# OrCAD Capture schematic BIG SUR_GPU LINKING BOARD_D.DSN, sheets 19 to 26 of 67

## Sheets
19 P19  PLX Switch-2 S4: size Custom
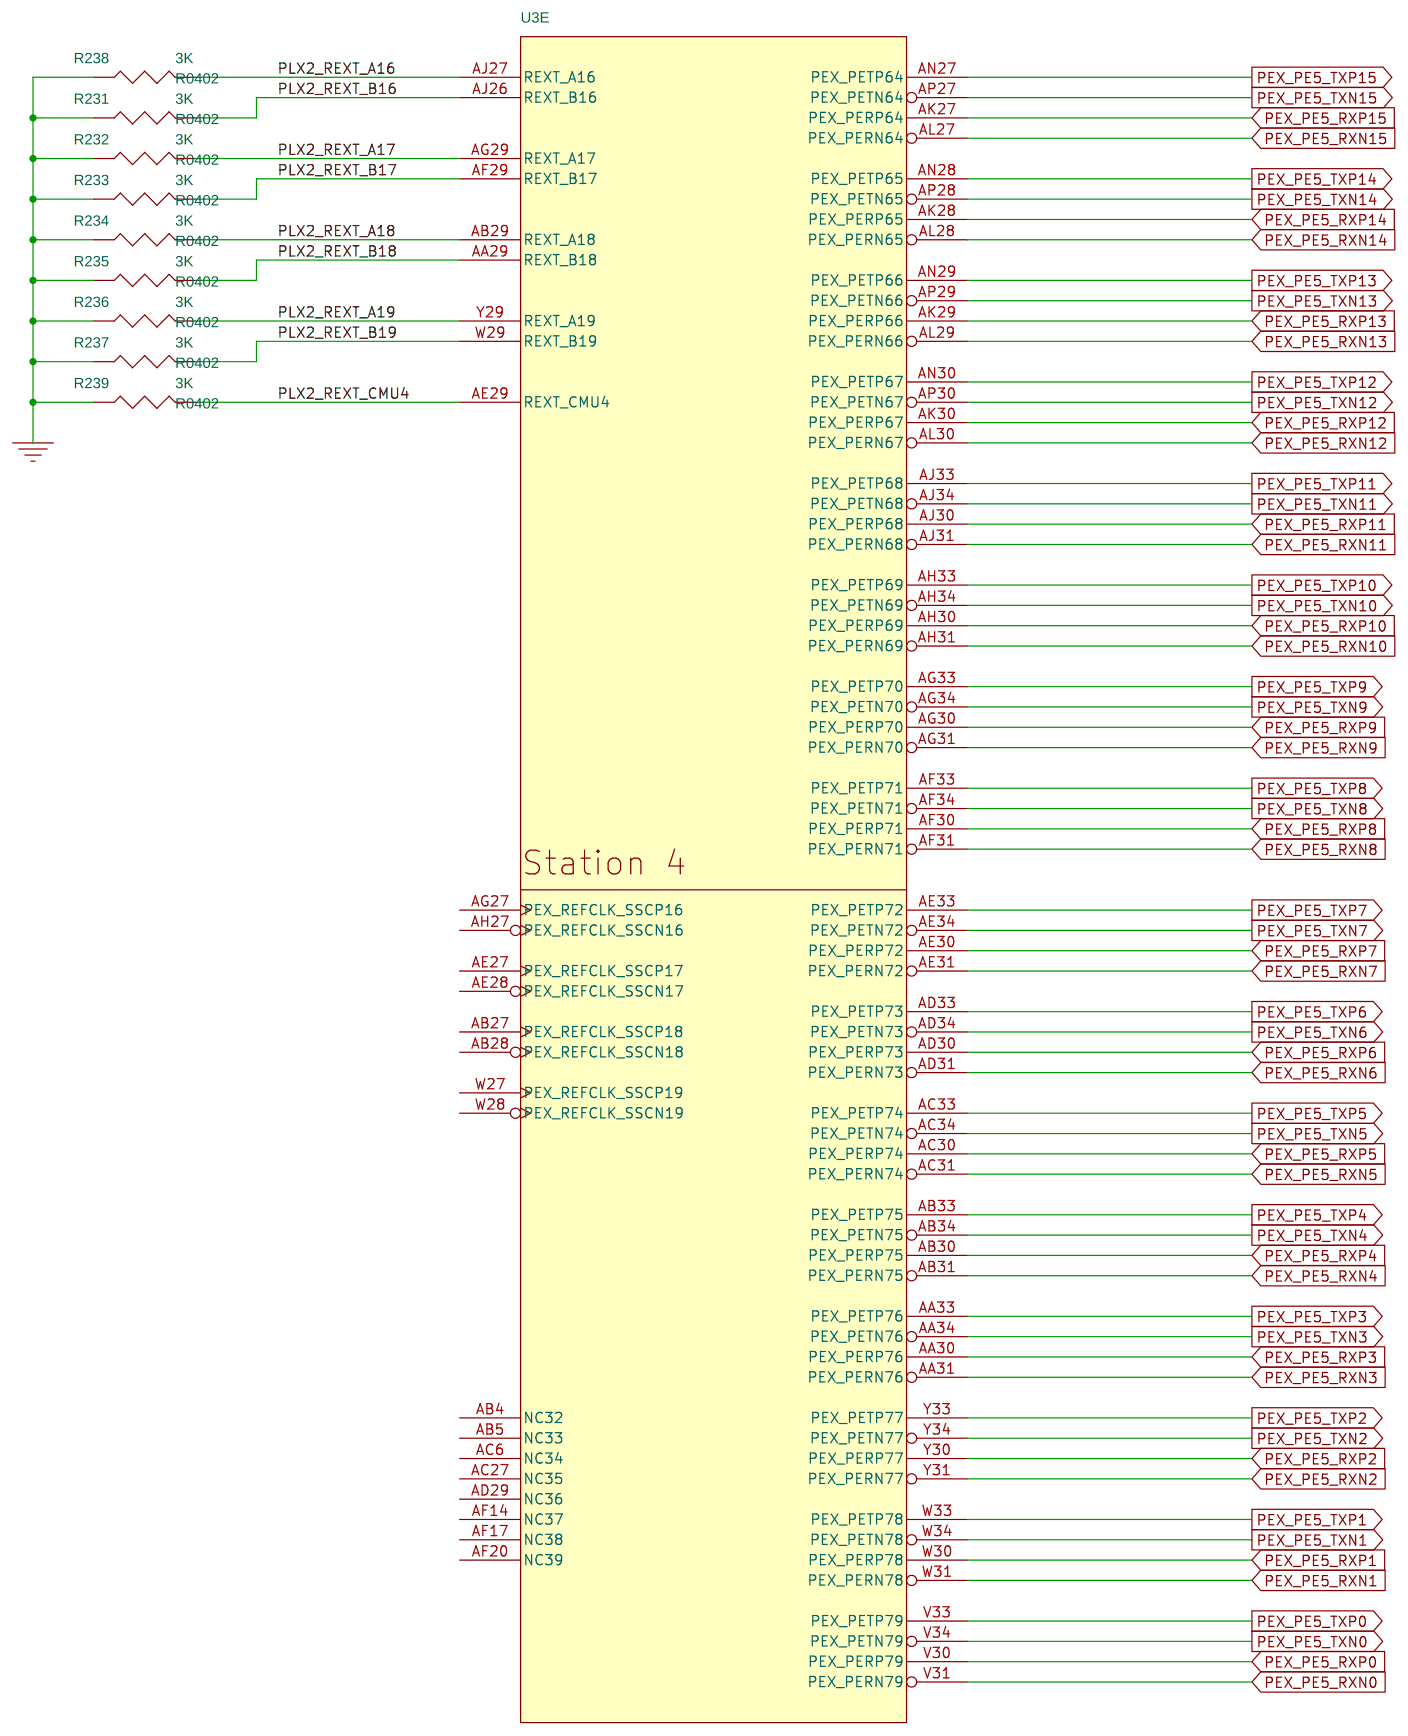
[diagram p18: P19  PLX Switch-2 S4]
20 P20  PLX Switch-2 S5: size Custom
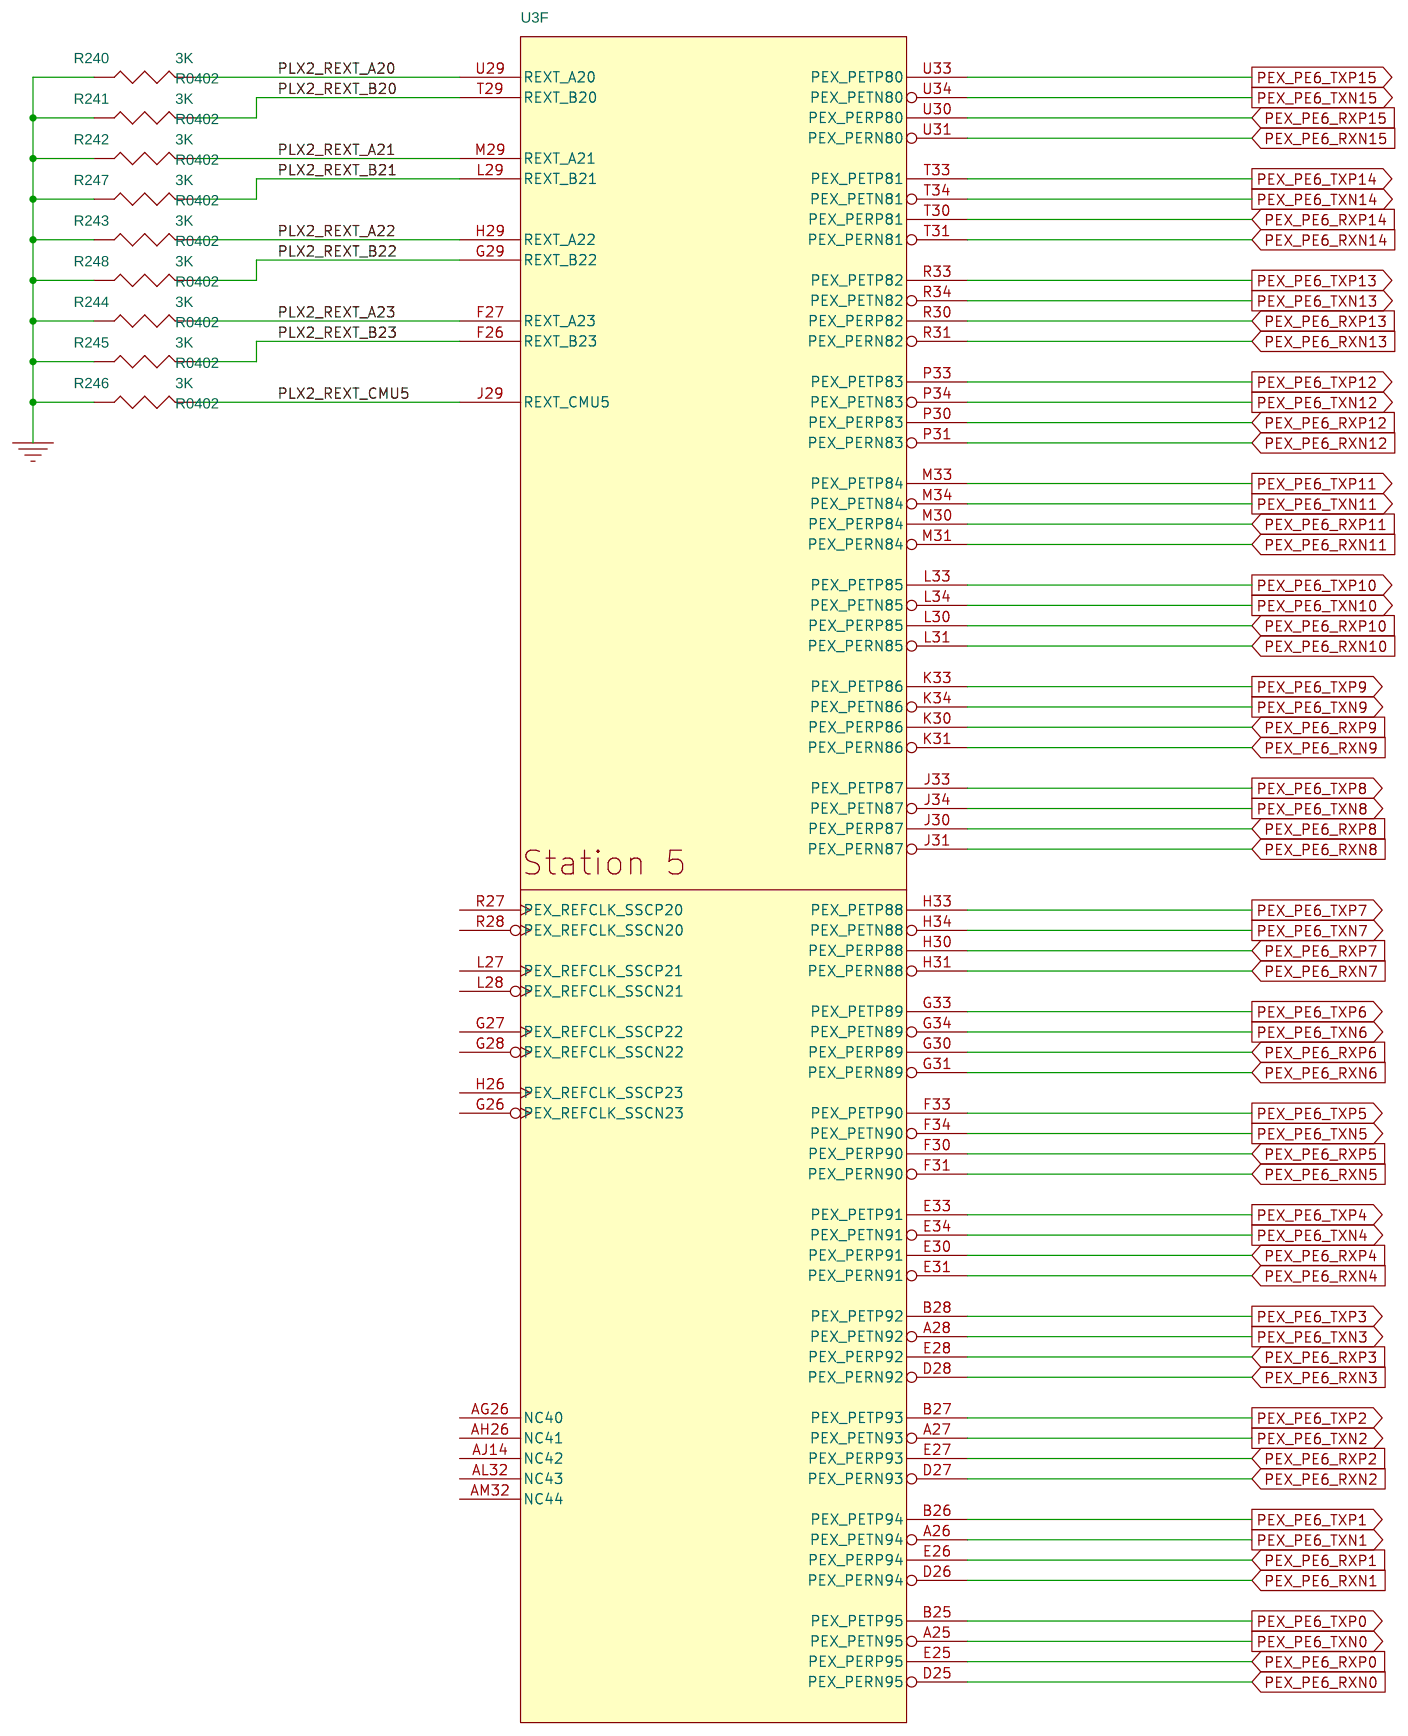
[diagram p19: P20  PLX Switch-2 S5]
21 P21  PLX Switch-2 Mode Select: size C
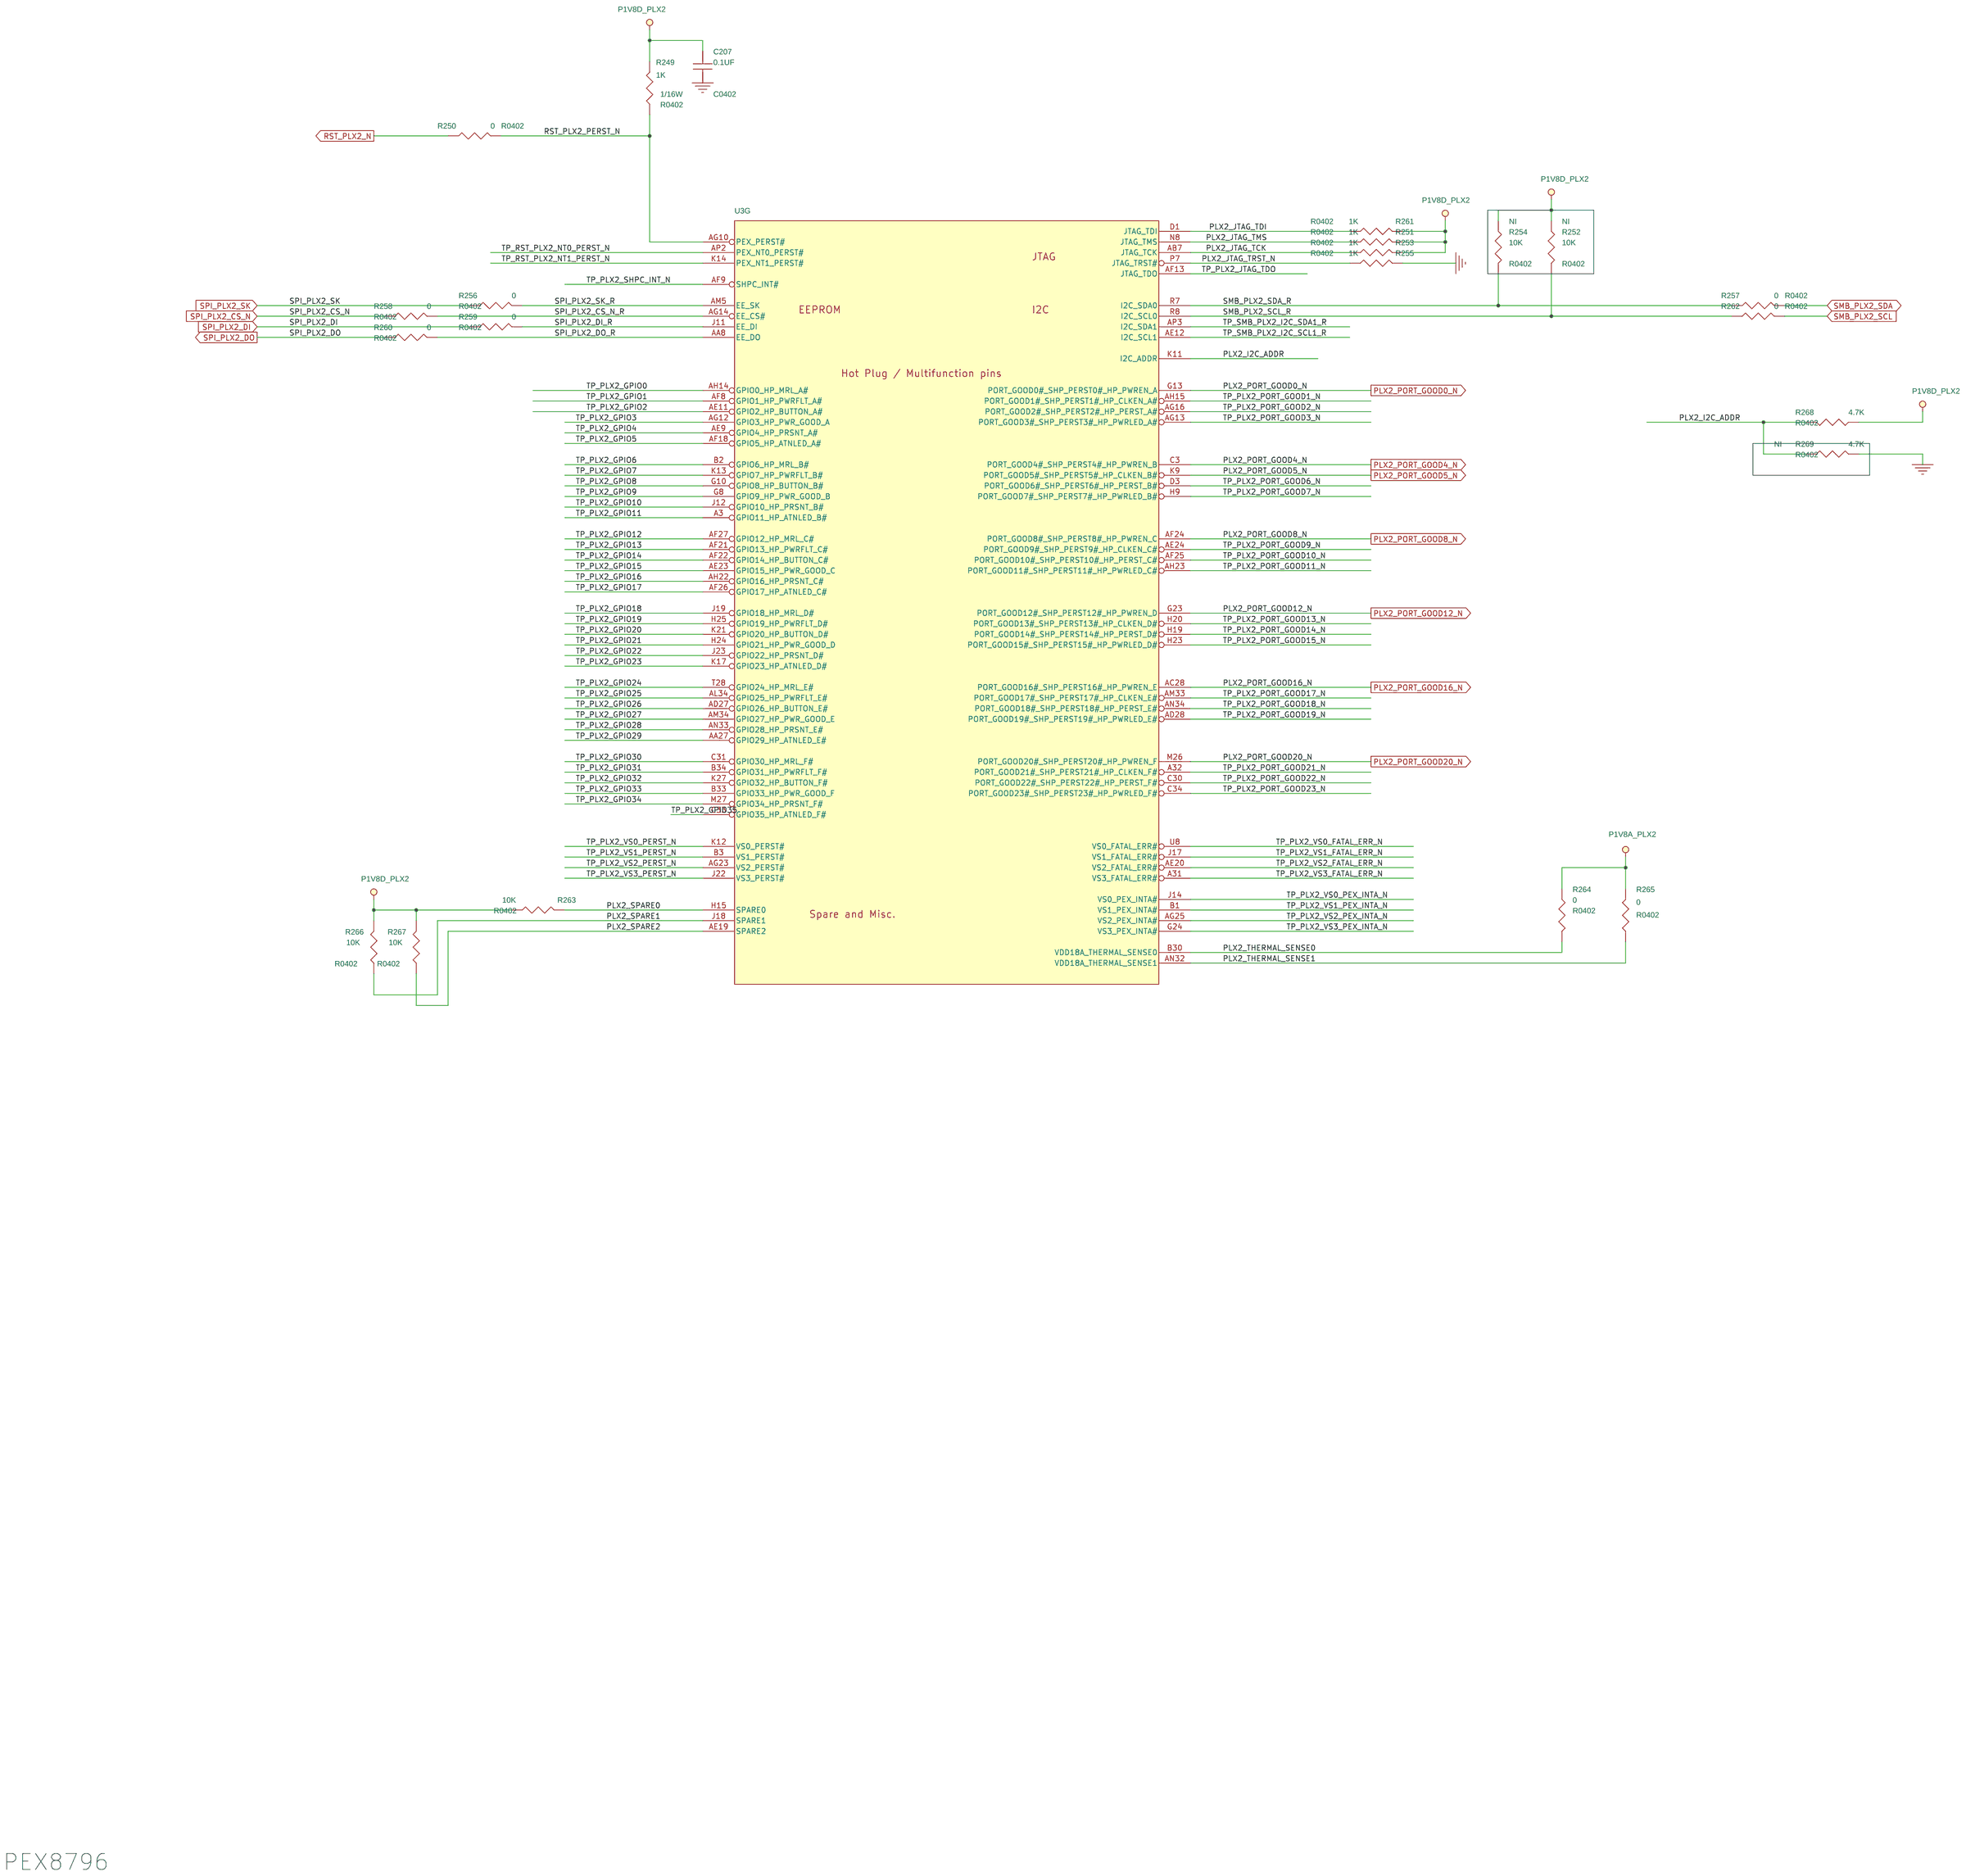
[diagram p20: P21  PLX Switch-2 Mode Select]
22 P22  PLX SW-2 EEPROM & Port LED: size C
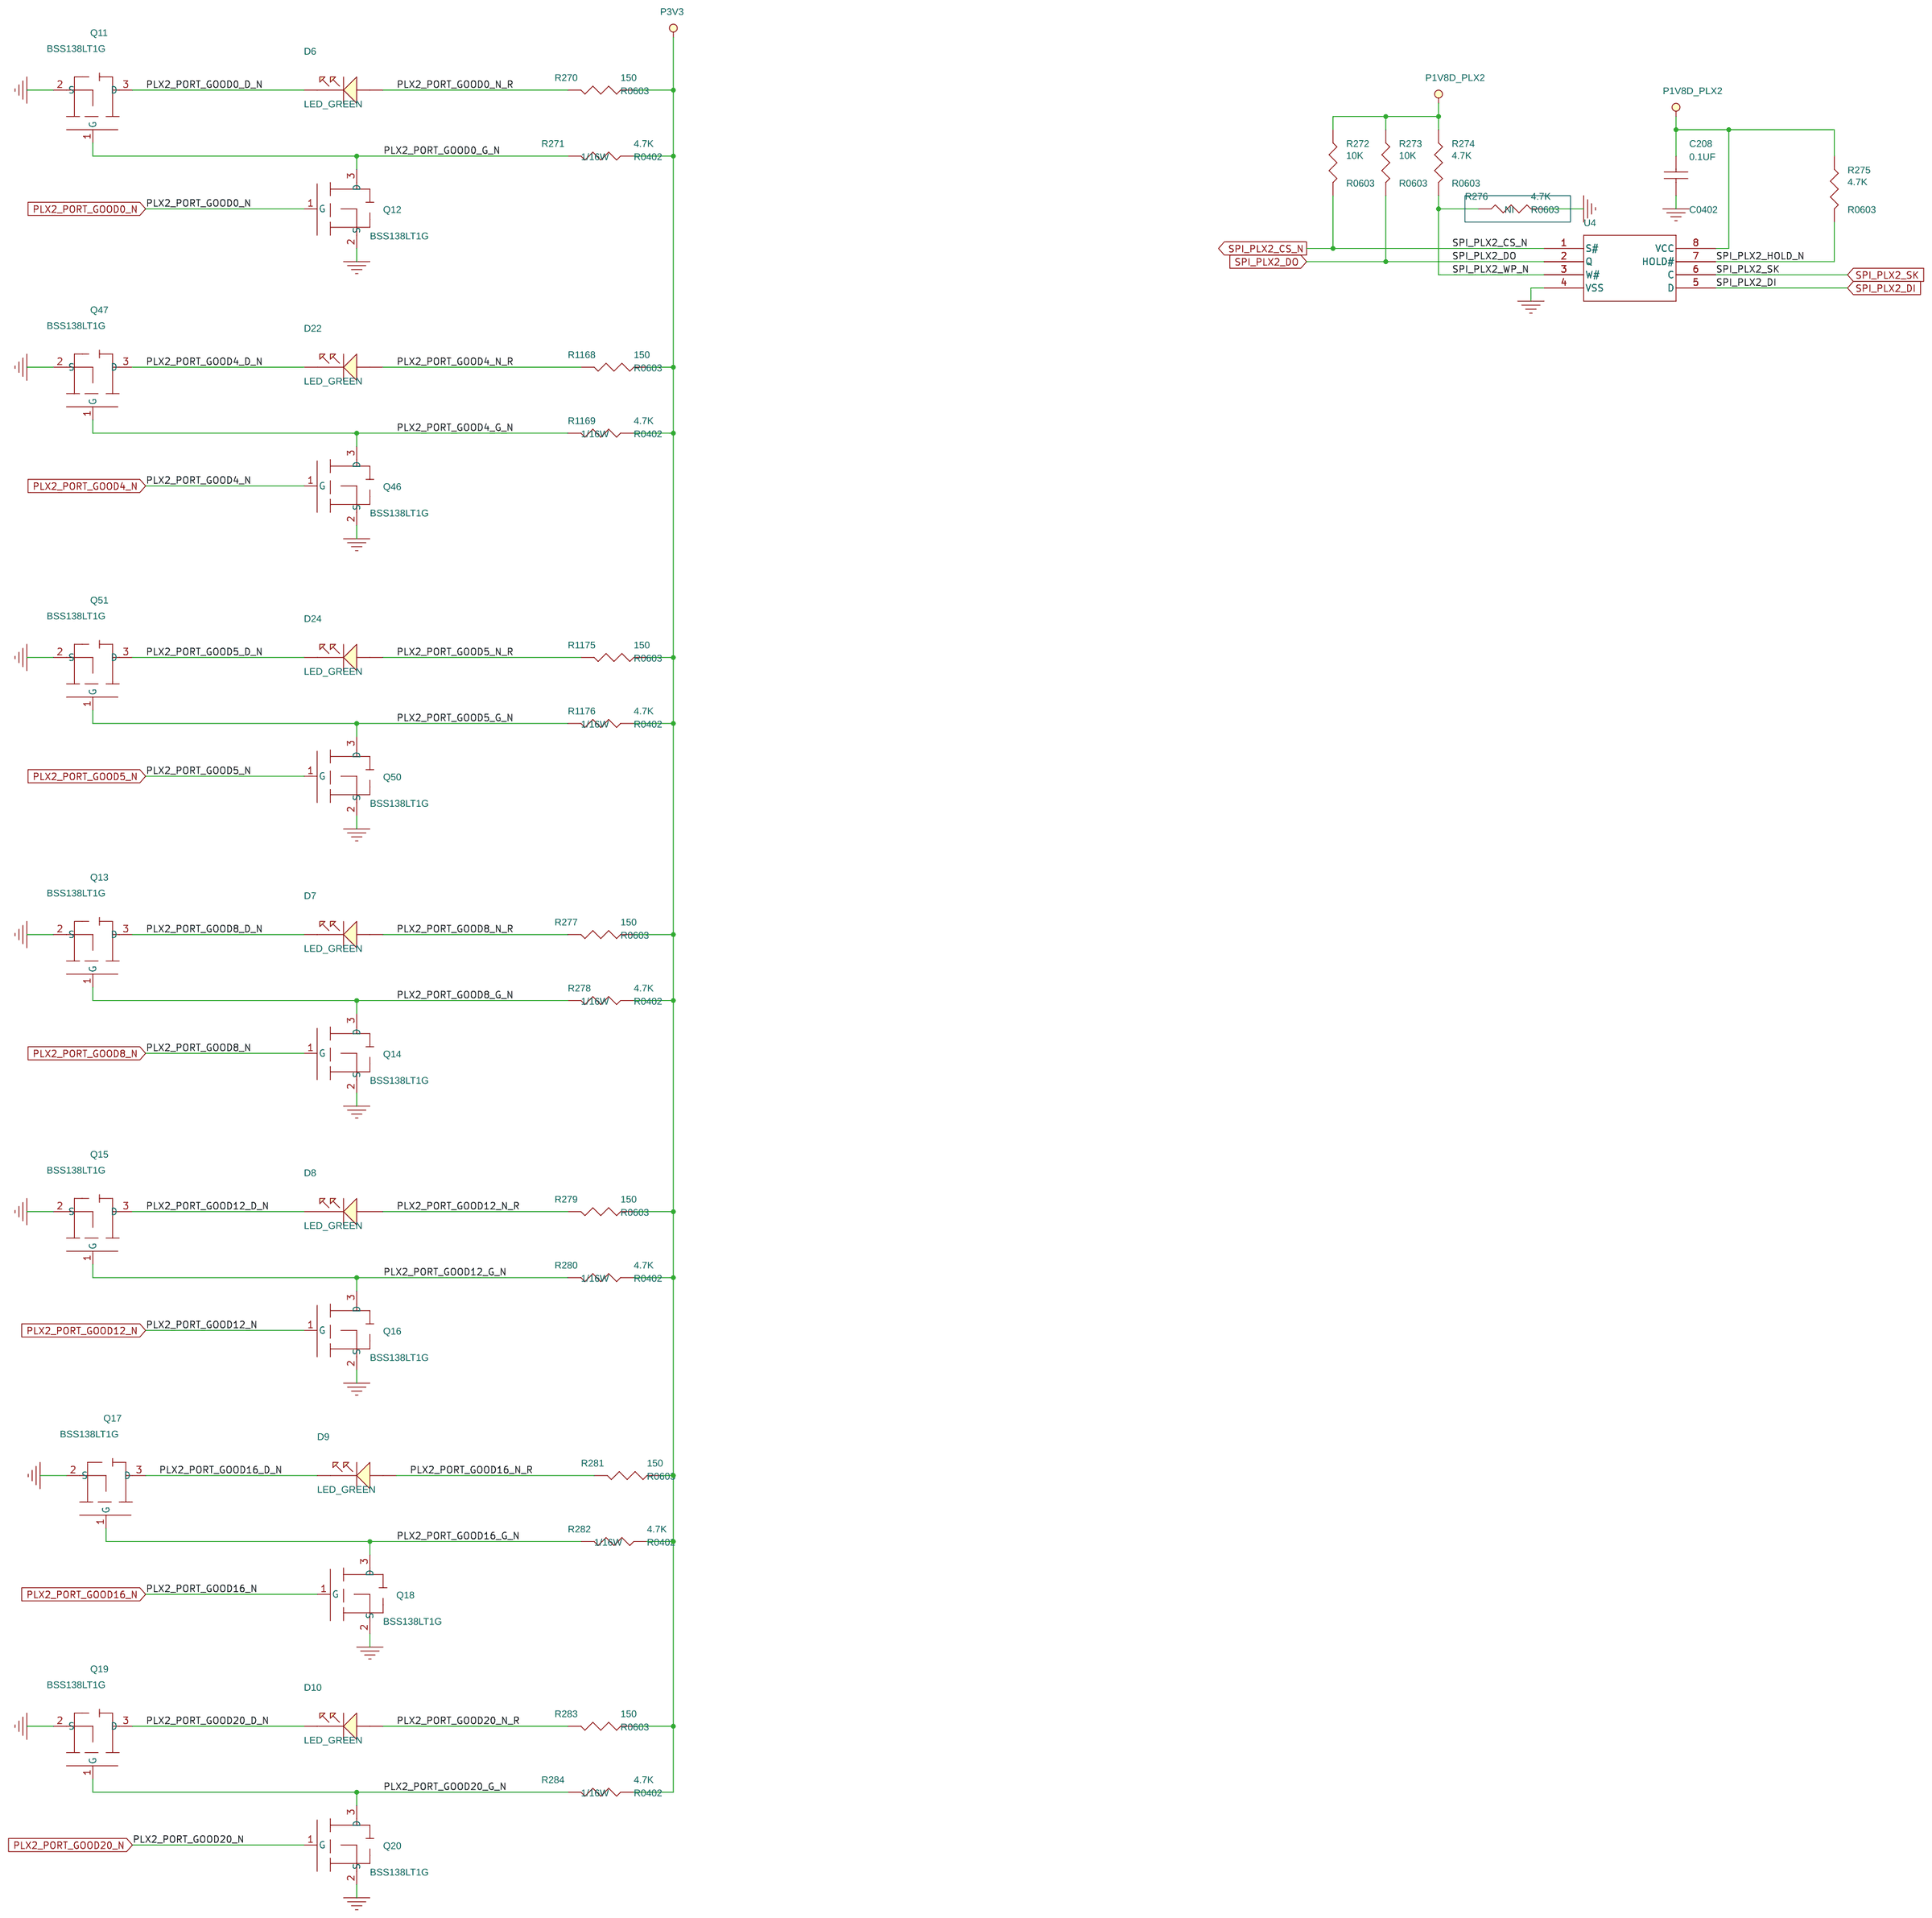
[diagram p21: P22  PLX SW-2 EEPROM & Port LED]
23 P23  PLX Switch-2 Straping: size Custom
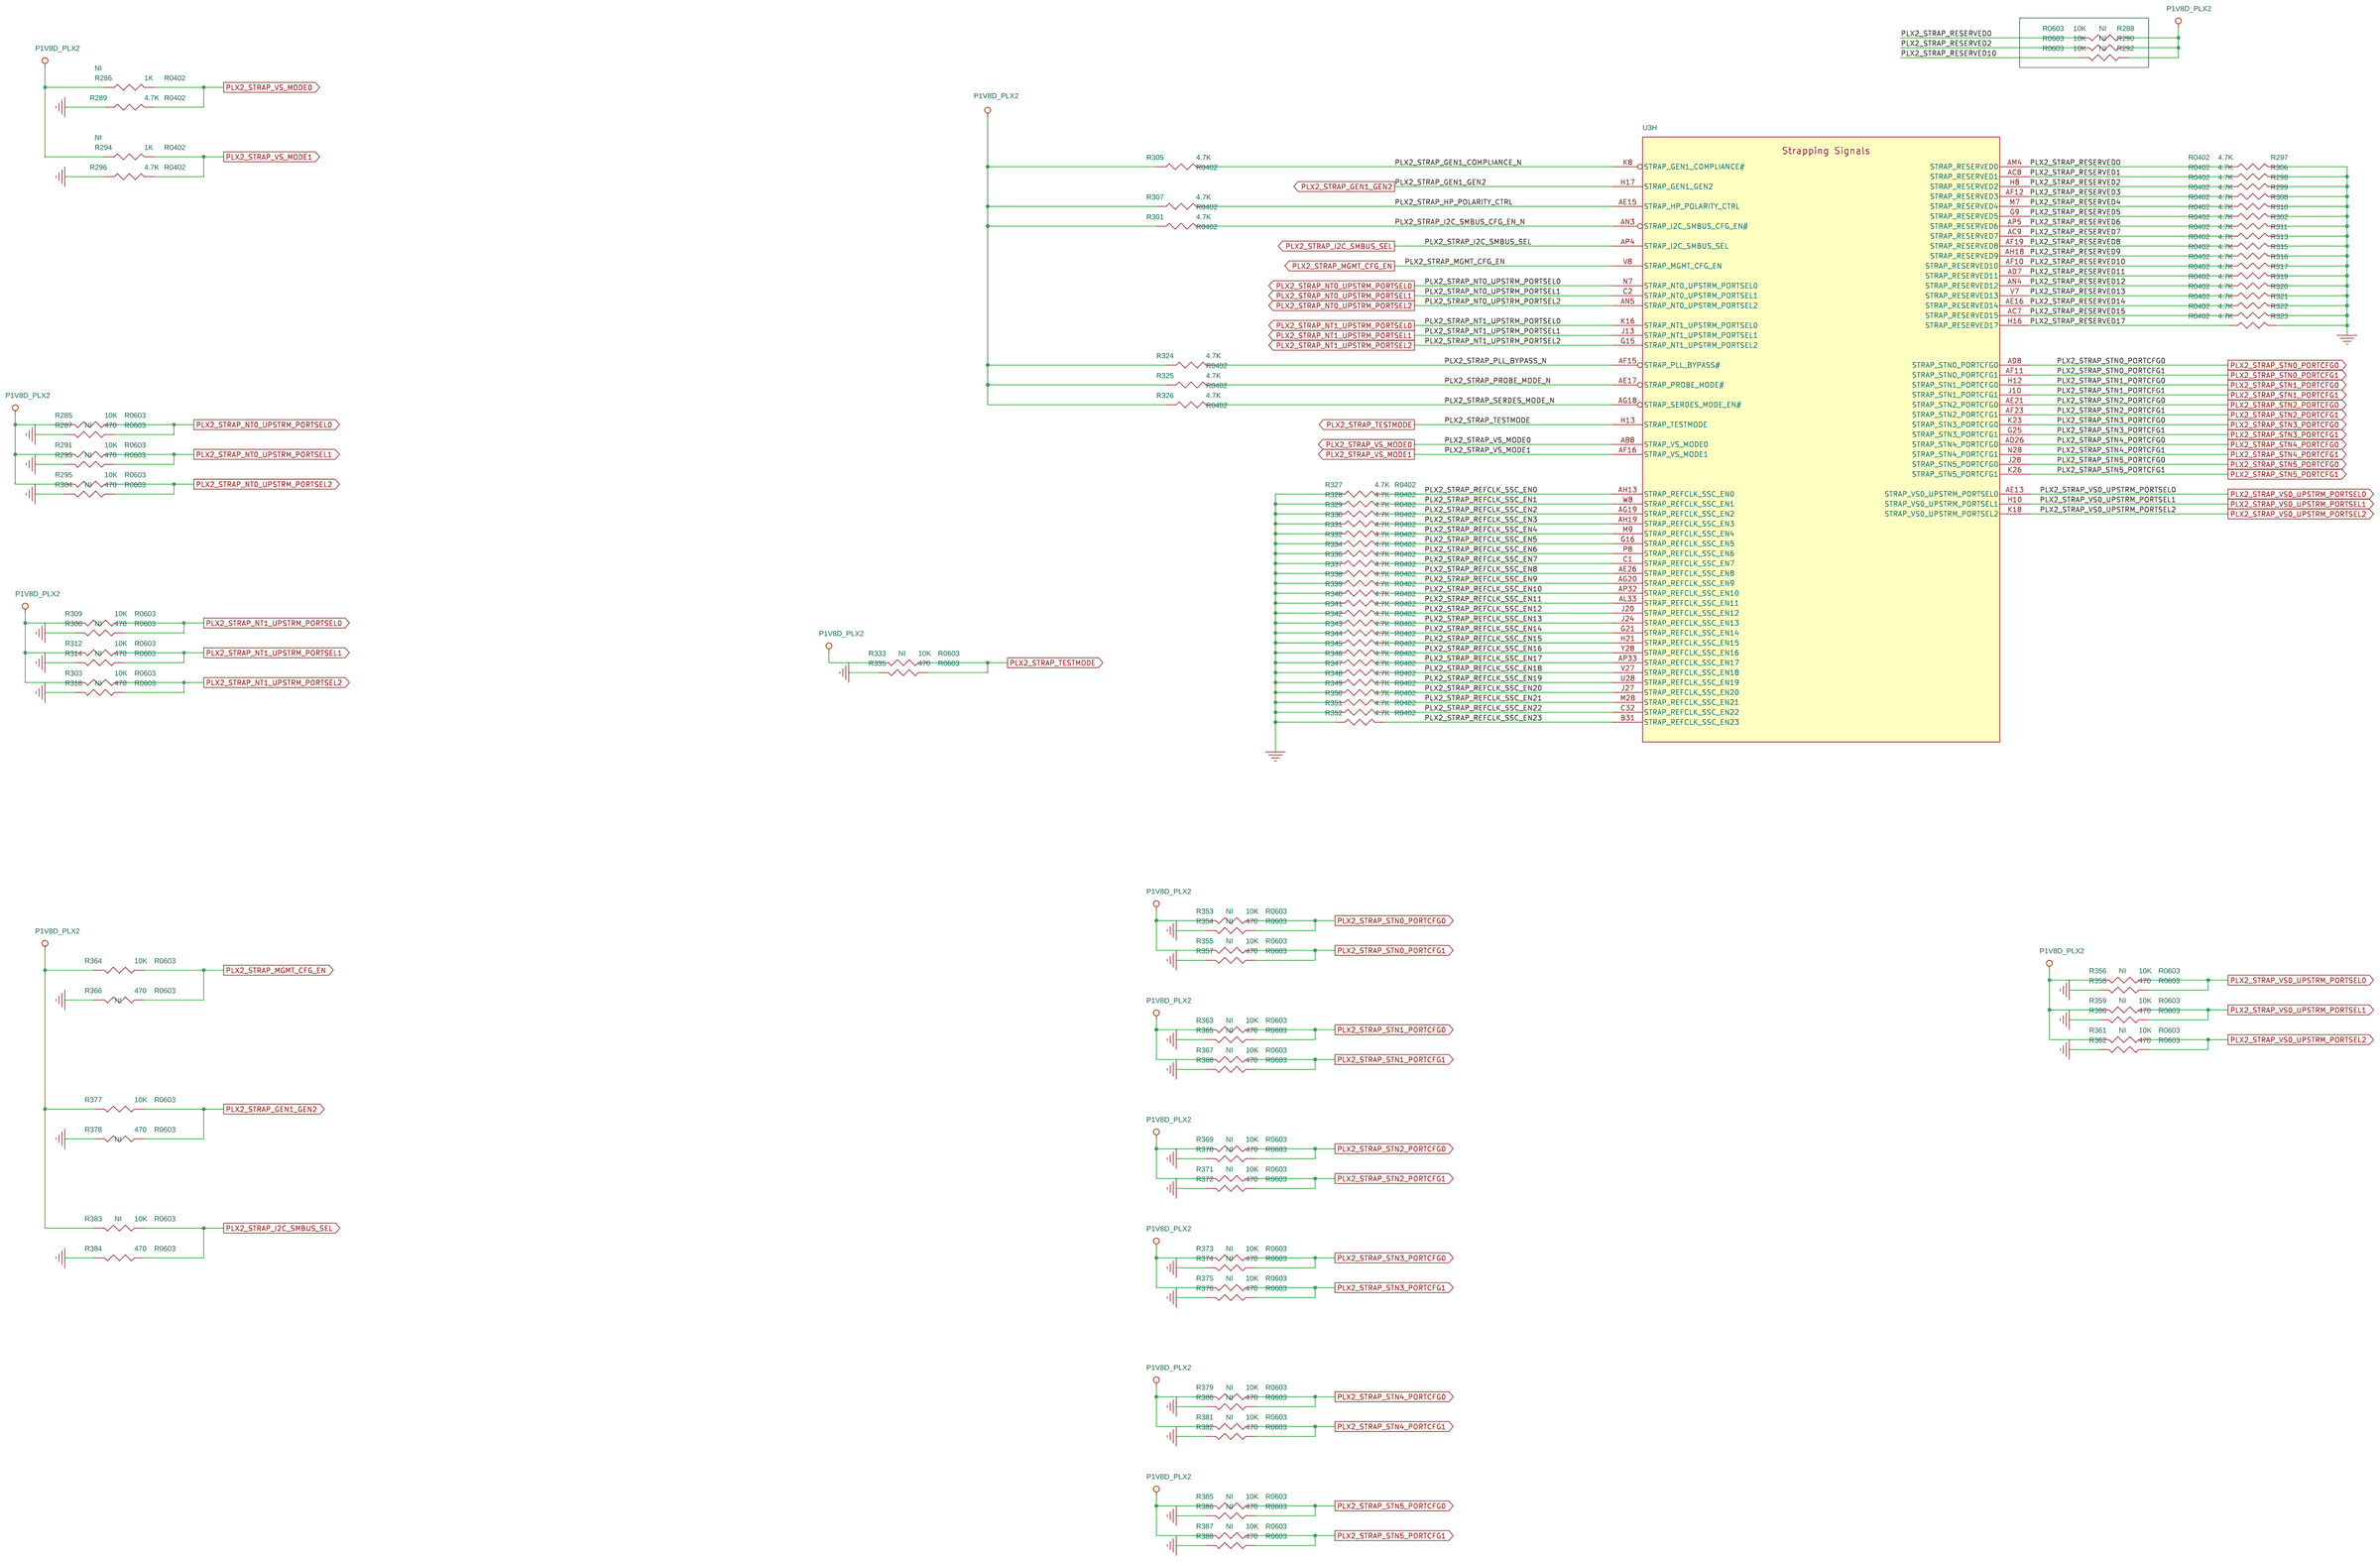
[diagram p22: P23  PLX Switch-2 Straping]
24 P24  PLX Switch-2 Power: size Custom
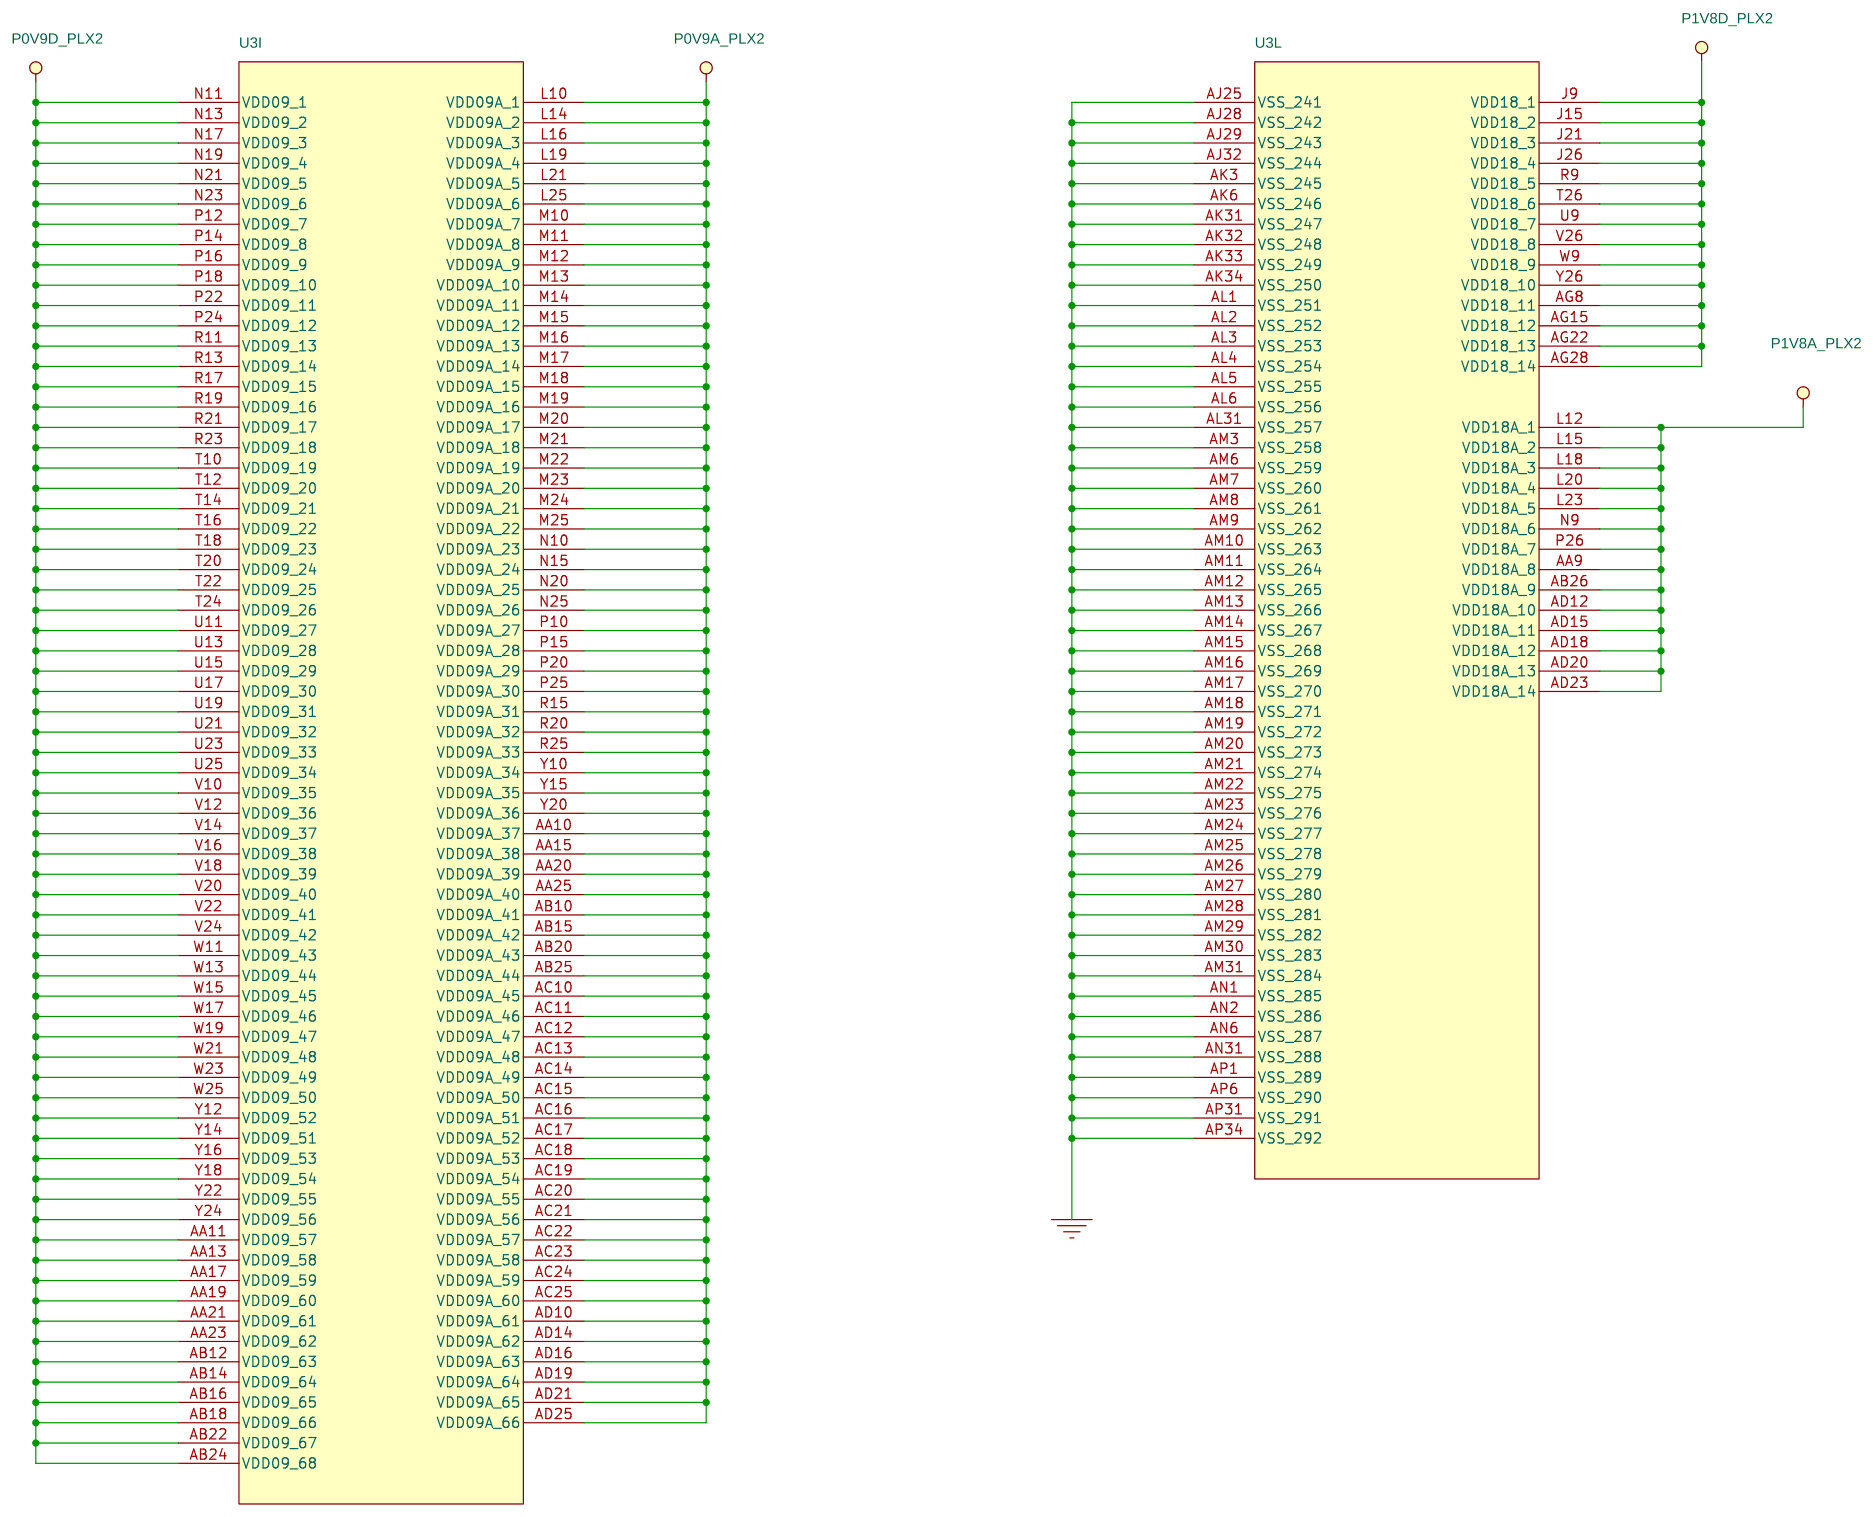
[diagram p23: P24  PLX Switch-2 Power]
25 P25  PLX Switch-2 VSS: size Custom
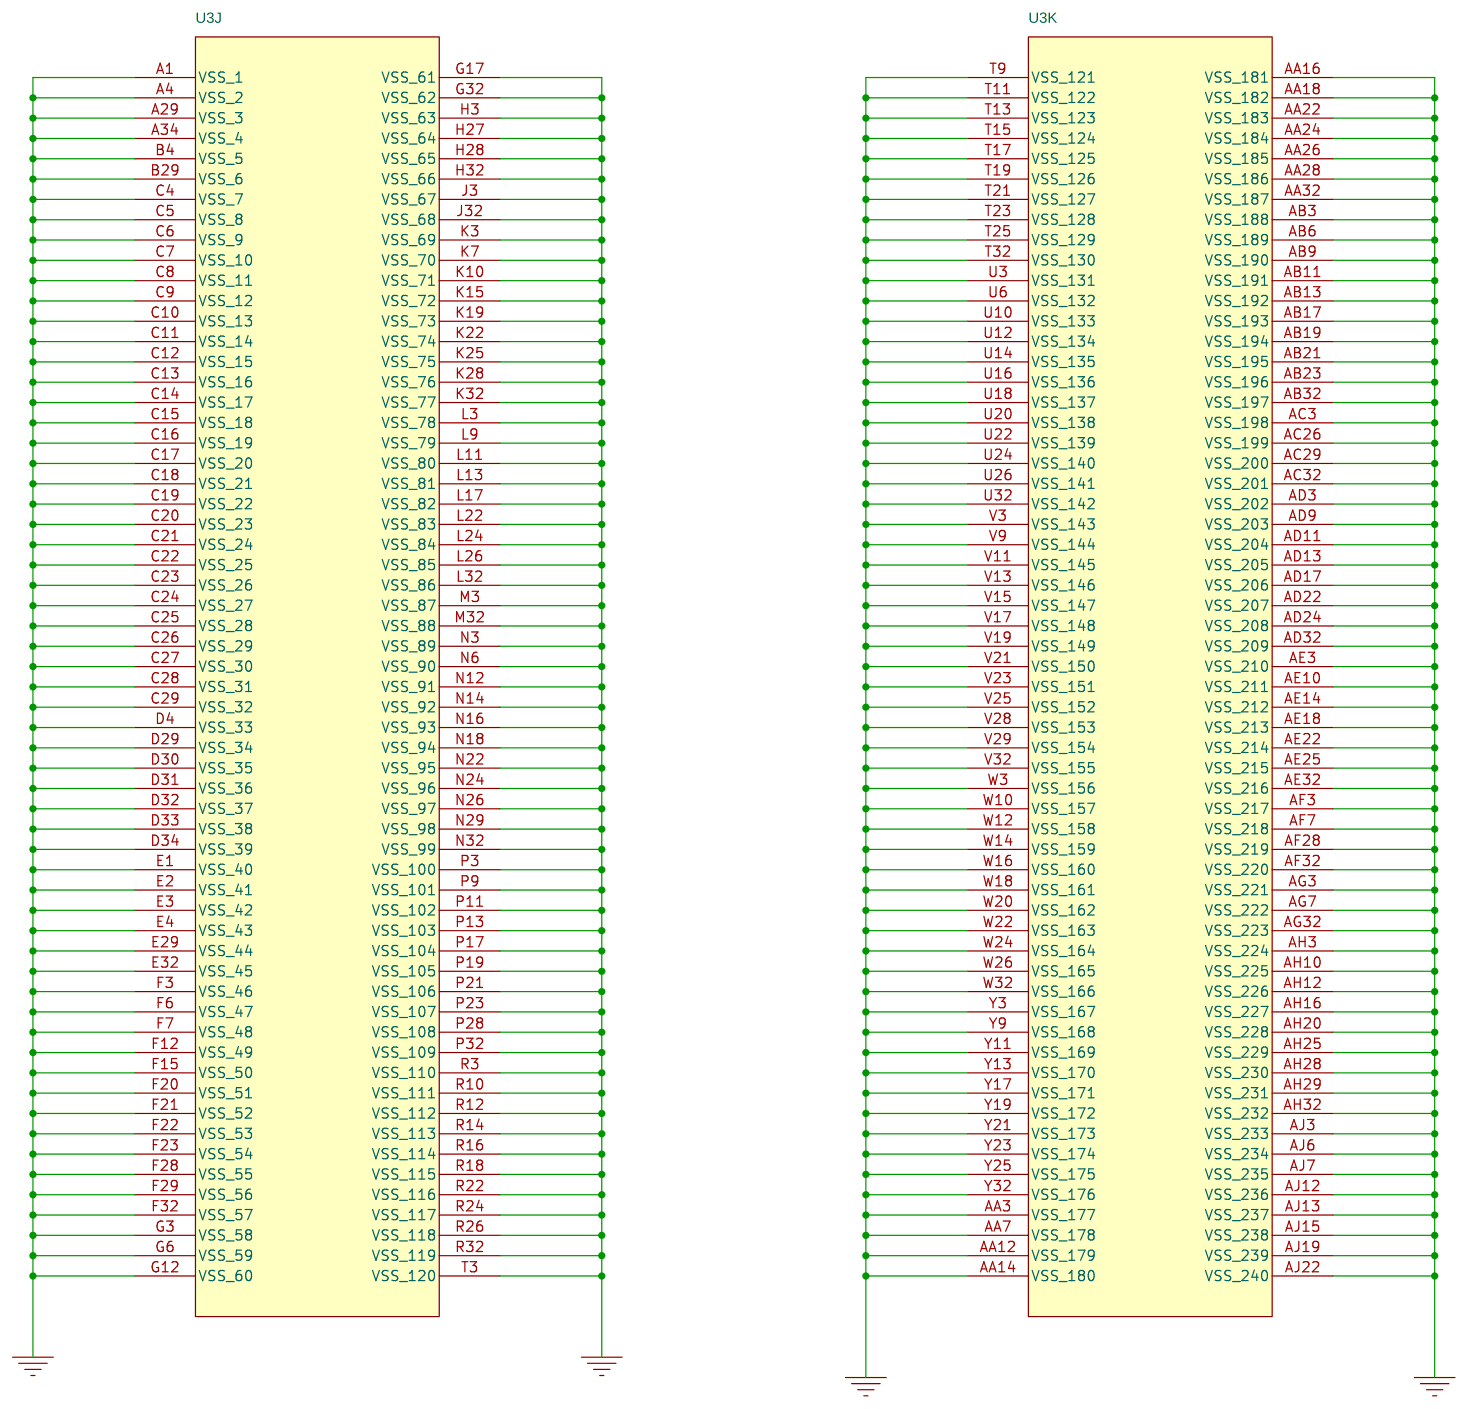
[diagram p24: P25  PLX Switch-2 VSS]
26 P26  PLX Switch-2 Decouping Cap: size Custom
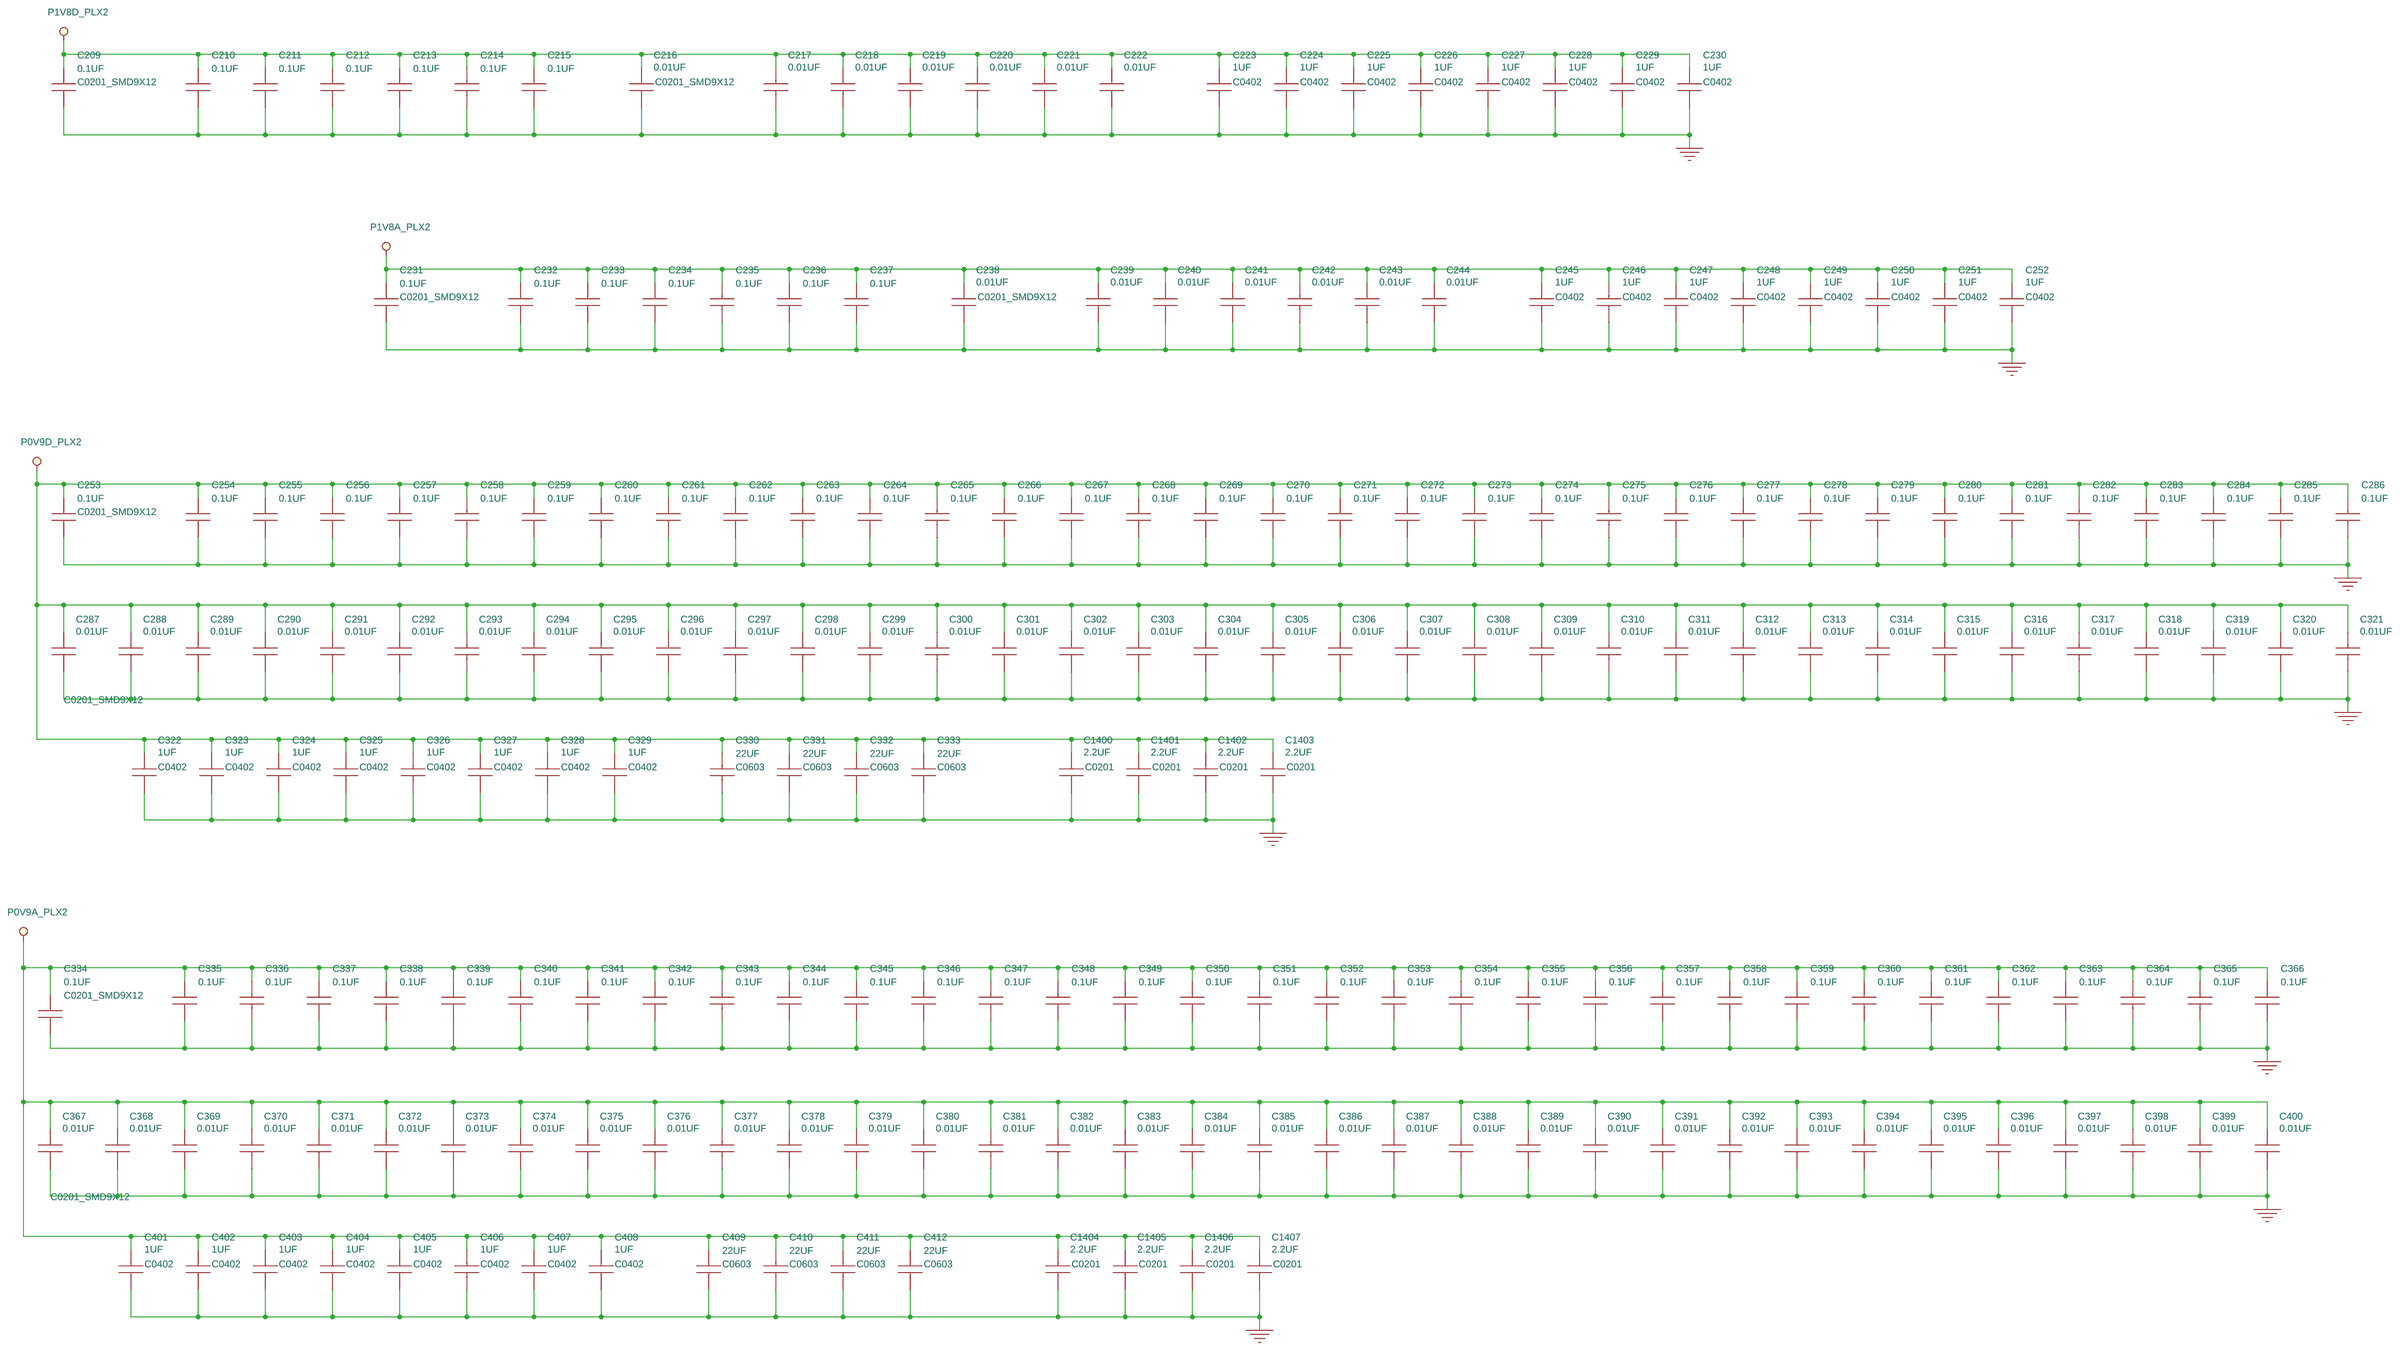
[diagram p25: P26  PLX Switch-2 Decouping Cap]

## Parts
sheet P19  PLX Switch-2 S4
R231  3K  [R0402]
R232  3K  [R0402]
R233  3K  [R0402]
R234  3K  [R0402]
R235  3K  [R0402]
R236  3K  [R0402]
R237  3K  [R0402]
R238  3K  [R0402]
R239  3K  [R0402]
sheet P20  PLX Switch-2 S5
R240  3K  [R0402]
R241  3K  [R0402]
R242  3K  [R0402]
R243  3K  [R0402]
R244  3K  [R0402]
R245  3K  [R0402]
R246  3K  [R0402]
R247  3K  [R0402]
R248  3K  [R0402]
sheet P21  PLX Switch-2 Mode Select
C207  0.1UF  [C0402]
R249  1K  [R0402]
R250  0  [R0402]
R251  1K  [R0402]
R252  10K  [R0402]
R253  1K  [R0402]
R254  10K  [R0402]
R255  1K  [R0402]
R256  0  [R0402]
R257  0  [R0402]
R258  0  [R0402]
R259  0  [R0402]
R260  0  [R0402]
R261  1K  [R0402]
R262  0  [R0402]
R263  10K  [R0402]
R264  0  [R0402]
R265  0  [R0402]
R266  10K  [R0402]
R267  10K  [R0402]
R268  4.7K  [R0402]
R269  4.7K  [R0402]
U3  PLX  [BGA1156]  (sections A,B,C,D,E,F,G,H,I,J,K,L)
sheet P22  PLX SW-2 EEPROM & Port LED
C208  0.1UF  [C0402]
D6  LED_GREEN  [LED_1221B]
D7  LED_GREEN  [LED_1221B]
D8  LED_GREEN  [LED_1221B]
D9  LED_GREEN  [LED_1221B]
D10  LED_GREEN  [LED_1221B]
D22  LED_GREEN  [LED_1221B]
D24  LED_GREEN  [LED_1221B]
Q11  BSS138LT1G  [SOT23_123]
Q12  BSS138LT1G  [SOT23_123]
Q13  BSS138LT1G  [SOT23_123]
Q14  BSS138LT1G  [SOT23_123]
Q15  BSS138LT1G  [SOT23_123]
Q16  BSS138LT1G  [SOT23_123]
Q17  BSS138LT1G  [SOT23_123]
Q18  BSS138LT1G  [SOT23_123]
Q19  BSS138LT1G  [SOT23_123]
Q20  BSS138LT1G  [SOT23_123]
Q46  BSS138LT1G  [SOT23_123]
Q47  BSS138LT1G  [SOT23_123]
Q50  BSS138LT1G  [SOT23_123]
Q51  BSS138LT1G  [SOT23_123]
R270  150  [R0603]
R271  4.7K  [R0402]
R272  10K  [R0603]
R273  10K  [R0603]
R274  4.7K  [R0603]
R275  4.7K  [R0603]
R276  4.7K  [R0603]
R277  150  [R0603]
R278  4.7K  [R0402]
R279  150  [R0603]
R280  4.7K  [R0402]
R281  150  [R0603]
R282  4.7K  [R0402]
R283  150  [R0603]
R284  4.7K  [R0402]
R1168  150  [R0603]
R1169  4.7K  [R0402]
R1175  150  [R0603]
R1176  4.7K  [R0402]
U4  IC  [SOIC8XH]
sheet P23  PLX Switch-2 Straping
R285  10K  [R0603]
R286  1K  [R0402]
R287  470  [R0603]
R288  10K  [R0603]
R289  4.7K  [R0402]
R290  10K  [R0603]
R291  10K  [R0603]
R292  10K  [R0603]
R293  470  [R0603]
R294  1K  [R0402]
R295  10K  [R0603]
R296  4.7K  [R0402]
R297  4.7K  [R0402]
R298  4.7K  [R0402]
R299  4.7K  [R0402]
R300  470  [R0603]
R301  4.7K  [R0402]
R302  4.7K  [R0402]
R303  10K  [R0603]
R304  470  [R0603]
R305  4.7K  [R0402]
R306  4.7K  [R0402]
R307  4.7K  [R0402]
R308  4.7K  [R0402]
R309  10K  [R0603]
R310  4.7K  [R0402]
R311  4.7K  [R0402]
R312  10K  [R0603]
R313  4.7K  [R0402]
R314  470  [R0603]
R315  4.7K  [R0402]
R316  4.7K  [R0402]
R317  4.7K  [R0402]
R318  470  [R0603]
R319  4.7K  [R0402]
R320  4.7K  [R0402]
R321  4.7K  [R0402]
R322  4.7K  [R0402]
R323  4.7K  [R0402]
R324  4.7K  [R0402]
R325  4.7K  [R0402]
R326  4.7K  [R0402]
R327  4.7K  [R0402]
R328  4.7K  [R0402]
R329  4.7K  [R0402]
R330  4.7K  [R0402]
R331  4.7K  [R0402]
R332  4.7K  [R0402]
R333  10K  [R0603]
R334  4.7K  [R0402]
R335  470  [R0603]
R336  4.7K  [R0402]
R337  4.7K  [R0402]
R338  4.7K  [R0402]
R339  4.7K  [R0402]
R340  4.7K  [R0402]
R341  4.7K  [R0402]
R342  4.7K  [R0402]
R343  4.7K  [R0402]
R344  4.7K  [R0402]
R345  4.7K  [R0402]
R346  4.7K  [R0402]
R347  4.7K  [R0402]
R348  4.7K  [R0402]
R349  4.7K  [R0402]
R350  4.7K  [R0402]
R351  4.7K  [R0402]
R352  4.7K  [R0402]
R353  10K  [R0603]
R354  470  [R0603]
R355  10K  [R0603]
R356  10K  [R0603]
R357  470  [R0603]
R358  470  [R0603]
R359  10K  [R0603]
R360  470  [R0603]
R361  10K  [R0603]
R362  470  [R0603]
R363  10K  [R0603]
R364  10K  [R0603]
R365  470  [R0603]
R366  470  [R0603]
R367  10K  [R0603]
R368  470  [R0603]
R369  10K  [R0603]
R370  470  [R0603]
R371  10K  [R0603]
R372  470  [R0603]
R373  10K  [R0603]
R374  470  [R0603]
R375  10K  [R0603]
R376  470  [R0603]
R377  10K  [R0603]
R378  470  [R0603]
R379  10K  [R0603]
R380  470  [R0603]
R381  10K  [R0603]
R382  470  [R0603]
R383  10K  [R0603]
R384  470  [R0603]
R385  10K  [R0603]
R386  470  [R0603]
R387  10K  [R0603]
R388  470  [R0603]
sheet P26  PLX Switch-2 Decouping Cap
C209  0.1UF  [C0201_SMD9X12]
C210  0.1UF  [C0201_SMD9X12]
C211  0.1UF  [C0201_SMD9X12]
C212  0.1UF  [C0201_SMD9X12]
C213  0.1UF  [C0201_SMD9X12]
C214  0.1UF  [C0201_SMD9X12]
C215  0.1UF  [C0201_SMD9X12]
C216  0.01UF  [C0201_SMD9X12]
C217  0.01UF  [C0201_SMD9X12]
C218  0.01UF  [C0201_SMD9X12]
C219  0.01UF  [C0201_SMD9X12]
C220  0.01UF  [C0201_SMD9X12]
C221  0.01UF  [C0201_SMD9X12]
C222  0.01UF  [C0201_SMD9X12]
C223  1UF  [C0402]
C224  1UF  [C0402]
C225  1UF  [C0402]
C226  1UF  [C0402]
C227  1UF  [C0402]
C228  1UF  [C0402]
C229  1UF  [C0402]
C230  1UF  [C0402]
C231  0.1UF  [C0201_SMD9X12]
C232  0.1UF  [C0201_SMD9X12]
C233  0.1UF  [C0201_SMD9X12]
C234  0.1UF  [C0201_SMD9X12]
C235  0.1UF  [C0201_SMD9X12]
C236  0.1UF  [C0201_SMD9X12]
C237  0.1UF  [C0201_SMD9X12]
C238  0.01UF  [C0201_SMD9X12]
C239  0.01UF  [C0201_SMD9X12]
C240  0.01UF  [C0201_SMD9X12]
C241  0.01UF  [C0201_SMD9X12]
C242  0.01UF  [C0201_SMD9X12]
C243  0.01UF  [C0201_SMD9X12]
C244  0.01UF  [C0201_SMD9X12]
C245  1UF  [C0402]
C246  1UF  [C0402]
C247  1UF  [C0402]
C248  1UF  [C0402]
C249  1UF  [C0402]
C250  1UF  [C0402]
C251  1UF  [C0402]
C252  1UF  [C0402]
C253  0.1UF  [C0201_SMD9X12]
C254  0.1UF  [C0201_SMD9X12]
C255  0.1UF  [C0201_SMD9X12]
C256  0.1UF  [C0201_SMD9X12]
C257  0.1UF  [C0201_SMD9X12]
C258  0.1UF  [C0201_SMD9X12]
C259  0.1UF  [C0201_SMD9X12]
C260  0.1UF  [C0201_SMD9X12]
C261  0.1UF  [C0201_SMD9X12]
C262  0.1UF  [C0201_SMD9X12]
C263  0.1UF  [C0201_SMD9X12]
C264  0.1UF  [C0201_SMD9X12]
C265  0.1UF  [C0201_SMD9X12]
C266  0.1UF  [C0201_SMD9X12]
C267  0.1UF  [C0201_SMD9X12]
C268  0.1UF  [C0201_SMD9X12]
C269  0.1UF  [C0201_SMD9X12]
C270  0.1UF  [C0201_SMD9X12]
C271  0.1UF  [C0201_SMD9X12]
C272  0.1UF  [C0201_SMD9X12]
C273  0.1UF  [C0201_SMD9X12]
C274  0.1UF  [C0201_SMD9X12]
C275  0.1UF  [C0201_SMD9X12]
C276  0.1UF  [C0201_SMD9X12]
C277  0.1UF  [C0201_SMD9X12]
C278  0.1UF  [C0201_SMD9X12]
C279  0.1UF  [C0201_SMD9X12]
C280  0.1UF  [C0201_SMD9X12]
C281  0.1UF  [C0201_SMD9X12]
C282  0.1UF  [C0201_SMD9X12]
C283  0.1UF  [C0201_SMD9X12]
C284  0.1UF  [C0201_SMD9X12]
C285  0.1UF  [C0201_SMD9X12]
C286  0.1UF  [C0201_SMD9X12]
C287  0.01UF  [C0201_SMD9X12]
C288  0.01UF  [C0201_SMD9X12]
C289  0.01UF  [C0201_SMD9X12]
C290  0.01UF  [C0201_SMD9X12]
C291  0.01UF  [C0201_SMD9X12]
C292  0.01UF  [C0201_SMD9X12]
C293  0.01UF  [C0201_SMD9X12]
C294  0.01UF  [C0201_SMD9X12]
C295  0.01UF  [C0201_SMD9X12]
C296  0.01UF  [C0201_SMD9X12]
C297  0.01UF  [C0201_SMD9X12]
C298  0.01UF  [C0201_SMD9X12]
C299  0.01UF  [C0201_SMD9X12]
C300  0.01UF  [C0201_SMD9X12]
C301  0.01UF  [C0201_SMD9X12]
C302  0.01UF  [C0201_SMD9X12]
C303  0.01UF  [C0201_SMD9X12]
C304  0.01UF  [C0201_SMD9X12]
C305  0.01UF  [C0201_SMD9X12]
C306  0.01UF  [C0201_SMD9X12]
C307  0.01UF  [C0201_SMD9X12]
C308  0.01UF  [C0201_SMD9X12]
C309  0.01UF  [C0201_SMD9X12]
C310  0.01UF  [C0201_SMD9X12]
C311  0.01UF  [C0201_SMD9X12]
C312  0.01UF  [C0201_SMD9X12]
C313  0.01UF  [C0201_SMD9X12]
C314  0.01UF  [C0201_SMD9X12]
C315  0.01UF  [C0201_SMD9X12]
C316  0.01UF  [C0201_SMD9X12]
C317  0.01UF  [C0201_SMD9X12]
C318  0.01UF  [C0201_SMD9X12]
C319  0.01UF  [C0201_SMD9X12]
C320  0.01UF  [C0201_SMD9X12]
C321  0.01UF  [C0201_SMD9X12]
C322  1UF  [C0402]
C323  1UF  [C0402]
C324  1UF  [C0402]
C325  1UF  [C0402]
C326  1UF  [C0402]
C327  1UF  [C0402]
C328  1UF  [C0402]
C329  1UF  [C0402]
C330  22UF  [C0603]
C331  22UF  [C0603]
C332  22UF  [C0603]
C333  22UF  [C0603]
C334  0.1UF  [C0201_SMD9X12]
C335  0.1UF  [C0201_SMD9X12]
C336  0.1UF  [C0201_SMD9X12]
C337  0.1UF  [C0201_SMD9X12]
C338  0.1UF  [C0201_SMD9X12]
C339  0.1UF  [C0201_SMD9X12]
C340  0.1UF  [C0201_SMD9X12]
C341  0.1UF  [C0201_SMD9X12]
C342  0.1UF  [C0201_SMD9X12]
C343  0.1UF  [C0201_SMD9X12]
C344  0.1UF  [C0201_SMD9X12]
C345  0.1UF  [C0201_SMD9X12]
C346  0.1UF  [C0201_SMD9X12]
C347  0.1UF  [C0201_SMD9X12]
C348  0.1UF  [C0201_SMD9X12]
C349  0.1UF  [C0201_SMD9X12]
C350  0.1UF  [C0201_SMD9X12]
C351  0.1UF  [C0201_SMD9X12]
C352  0.1UF  [C0201_SMD9X12]
C353  0.1UF  [C0201_SMD9X12]
C354  0.1UF  [C0201_SMD9X12]
C355  0.1UF  [C0201_SMD9X12]
C356  0.1UF  [C0201_SMD9X12]
C357  0.1UF  [C0201_SMD9X12]
C358  0.1UF  [C0201_SMD9X12]
C359  0.1UF  [C0201_SMD9X12]
C360  0.1UF  [C0201_SMD9X12]
C361  0.1UF  [C0201_SMD9X12]
C362  0.1UF  [C0201_SMD9X12]
C363  0.1UF  [C0201_SMD9X12]
C364  0.1UF  [C0201_SMD9X12]
C365  0.1UF  [C0201_SMD9X12]
C366  0.1UF  [C0201_SMD9X12]
C367  0.01UF  [C0201_SMD9X12]
C368  0.01UF  [C0201_SMD9X12]
C369  0.01UF  [C0201_SMD9X12]
C370  0.01UF  [C0201_SMD9X12]
C371  0.01UF  [C0201_SMD9X12]
C372  0.01UF  [C0201_SMD9X12]
C373  0.01UF  [C0201_SMD9X12]
C374  0.01UF  [C0201_SMD9X12]
C375  0.01UF  [C0201_SMD9X12]
C376  0.01UF  [C0201_SMD9X12]
C377  0.01UF  [C0201_SMD9X12]
C378  0.01UF  [C0201_SMD9X12]
C379  0.01UF  [C0201_SMD9X12]
C380  0.01UF  [C0201_SMD9X12]
C381  0.01UF  [C0201_SMD9X12]
C382  0.01UF  [C0201_SMD9X12]
C383  0.01UF  [C0201_SMD9X12]
C384  0.01UF  [C0201_SMD9X12]
C385  0.01UF  [C0201_SMD9X12]
C386  0.01UF  [C0201_SMD9X12]
C387  0.01UF  [C0201_SMD9X12]
C388  0.01UF  [C0201_SMD9X12]
C389  0.01UF  [C0201_SMD9X12]
C390  0.01UF  [C0201_SMD9X12]
C391  0.01UF  [C0201_SMD9X12]
C392  0.01UF  [C0201_SMD9X12]
C393  0.01UF  [C0201_SMD9X12]
C394  0.01UF  [C0201_SMD9X12]
C395  0.01UF  [C0201_SMD9X12]
C396  0.01UF  [C0201_SMD9X12]
C397  0.01UF  [C0201_SMD9X12]
C398  0.01UF  [C0201_SMD9X12]
C399  0.01UF  [C0201_SMD9X12]
C400  0.01UF  [C0201_SMD9X12]
C401  1UF  [C0402]
C402  1UF  [C0402]
C403  1UF  [C0402]
C404  1UF  [C0402]
C405  1UF  [C0402]
C406  1UF  [C0402]
C407  1UF  [C0402]
C408  1UF  [C0402]
C409  22UF  [C0603]
C410  22UF  [C0603]
C411  22UF  [C0603]
C412  22UF  [C0603]
C1400  2.2UF  [C0201]
C1401  2.2UF  [C0201]
C1402  2.2UF  [C0201]
C1403  2.2UF  [C0201]
C1404  2.2UF  [C0201]
C1405  2.2UF  [C0201]
C1406  2.2UF  [C0201]
C1407  2.2UF  [C0201]

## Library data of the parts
R231-R251 R253 R255-R268 R271 R278 R280 R282 R284 R289 R296-R299 R301 R302 R305-R308 R310 R311 R313 R315-R317 R319-R332 R334 R336-R352 R1169 R1176 = R: Part_Type: *LF_Resistor; WATTAGE: 1/16W
C207 C208 C223-C230 C245-C252 C322-C329 C401-C408 = CAP_NP: Part_Type: *LF_C0402
R252 R254 R269 R286 R294 = R: Not_insert: NI; Part_Type: *LF_Resistor; WATTAGE: 1/16W
U3 = PEX8796AA80BIG: Part_Type: *LF_Chipset
D6-D10 D22 D24 = LED_12: Part_Type: Semiconductor
Q11-Q20 Q46 Q47 Q50 Q51 = BSS123: Part_Type: *LF_Semiconductor
R270 R272-R275 R277 R279 R281 R283 R285 R291 R295 R303 R309 R312 R335 R357 R358 R360 R362 R364 R368 R372 R376 R377 R382 R384 R388 R1168 R1175 = R: Part_Type: *LF_Resistor; WATTAGE: 1/10W
R276 R287 R288 R290 R292 R293 R300 R304 R314 R318 R333 R353-R356 R359 R361 R363 R365-R367 R369-R371 R373-R375 R378-R381 R383 R385-R387 = R: Not_insert: NI; Part_Type: *LF_Resistor; WATTAGE: 1/10W
U4 = M95512RMN6TP: Part_Type: *LF_Chipset
C209-C222 C231-C244 C253-C321 C334-C400 C1400-C1407 = CAP_NP: Part_Type: *LF_C0201
C330-C333 C409-C412 = CAP_NP: Part_Type: *LF_C0603

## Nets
GND: C207.2 C208.2 C209.2 C210.2 C211.2 C212.2 C213.2 C214.2 C215.2 C216.2 C217.2 C218.2 C219.2 C220.2 C221.2 C222.2 C223.2 C224.2 C225.2 C226.2 C227.2 C228.2 C229.2 C230.2 C231.2 C232.2 C233.2 C234.2 C235.2 C236.2 C237.2 C238.2 C239.2 C240.2 C241.2 C242.2 C243.2 C244.2 C245.2 C246.2 C247.2 C248.2 C249.2 C250.2 C251.2 C252.2 C253.2 C254.2 C255.2 C256.2 C257.2 C258.2 C259.2 C260.2 C261.2 C262.2 C263.2 C264.2 C265.2 C266.2 C267.2 C268.2 C269.2 C270.2 C271.2 C272.2 C273.2 C274.2 C275.2 C276.2 C277.2 C278.2 C279.2 C280.2 C281.2 C282.2 C283.2 C284.2 C285.2 C286.2 C287.2 C288.2 C289.2 C290.2 C291.2 C292.2 C293.2 C294.2 C295.2 C296.2 C297.2 C298.2 C299.2 C300.2 C301.2 C302.2 C303.2 C304.2 C305.2 C306.2 C307.2 C308.2 C309.2 C310.2 C311.2 C312.2 C313.2 C314.2 C315.2 C316.2 C317.2 C318.2 C319.2 C320.2 C321.2 C322.2 C323.2 C324.2 C325.2 C326.2 C327.2 C328.2 C329.2 C330.2 C331.2 C332.2 C333.2 C334.2 C335.2 C336.2 C337.2 C338.2 C339.2 C340.2 C341.2 C342.2 C343.2 C344.2 C345.2 C346.2 C347.2 C348.2 C349.2 C350.2 C351.2 C352.2 C353.2 C354.2 C355.2 C356.2 C357.2 C358.2 C359.2 C360.2 C361.2 C362.2 C363.2 C364.2 C365.2 C366.2 C367.2 C368.2 C369.2 C370.2 C371.2 C372.2 C373.2 C374.2 C375.2 C376.2 C377.2 C378.2 C379.2 C380.2 C381.2 C382.2 C383.2 C384.2 C385.2 C386.2 C387.2 C388.2 C389.2 C390.2 C391.2 C392.2 C393.2 C394.2 C395.2 C396.2 C397.2 C398.2 C399.2 C400.2 C401.2 C402.2 C403.2 C404.2 C405.2 C406.2 C407.2 C408.2 C409.2 C410.2 C411.2 C412.2 C1400.2 C1401.2 C1402.2 C1403.2 C1404.2 C1405.2 C1406.2 C1407.2 Q11.2(S) Q12.2(S) Q13.2(S) Q14.2(S) Q15.2(S) Q16.2(S) Q17.2(S) Q18.2(S) Q19.2(S) Q20.2(S) Q46.2(S) Q47.2(S) Q50.2(S) Q51.2(S) R231.1 R232.1 R233.1 R234.1 R235.1 R236.1 R237.1 R238.1 R239.1 R240.1 R241.1 R242.1 R243.1 R244.1 R245.1 R246.1 R247.1 R248.1 R255.1 R269.2 R276.2 R287.2 R289.1 R293.2 R296.1 R297.1 R298.1 R299.1 R300.2 R302.1 R304.2 R306.1 R308.1 R310.1 R311.1 R313.1 R314.2 R315.1 R316.1 R317.1 R318.2 R319.1 R320.1 R321.1 R322.1 R323.1 R327.1 R328.1 R329.1 R330.1 R331.1 R332.1 R334.1 R335.2 R336.1 R337.1 R338.1 R339.1 R340.1 R341.1 R342.1 R343.1 R344.1 R345.1 R346.1 R347.1 R348.1 R349.1 R350.1 R351.1 R352.1 R354.2 R357.2 R358.2 R360.2 R362.2 R365.2 R366.2 R368.2 R370.2 R372.2 R374.2 R376.2 R378.2 R380.2 R382.2 R384.2 R386.2 R388.2 U3.A1(VSS_1) U3.A4(VSS_2) U3.A29(VSS_3) U3.A34(VSS_4) U3.AA3(VSS_177) U3.AA7(VSS_178) U3.AA12(VSS_179) U3.AA14(VSS_180) U3.AA16(VSS_181) U3.AA18(VSS_182) U3.AA22(VSS_183) U3.AA24(VSS_184) U3.AA26(VSS_185) U3.AA28(VSS_186) U3.AA32(VSS_187) U3.AB3(VSS_188) U3.AB6(VSS_189) U3.AB9(VSS_190) U3.AB11(VSS_191) U3.AB13(VSS_192) U3.AB17(VSS_193) U3.AB19(VSS_194) U3.AB21(VSS_195) U3.AB23(VSS_196) U3.AB32(VSS_197) U3.AC3(VSS_198) U3.AC26(VSS_199) U3.AC29(VSS_200) U3.AC32(VSS_201) U3.AD3(VSS_202) U3.AD9(VSS_203) U3.AD11(VSS_204) U3.AD13(VSS_205) U3.AD17(VSS_206) U3.AD22(VSS_207) U3.AD24(VSS_208) U3.AD32(VSS_209) U3.AE3(VSS_210) U3.AE10(VSS_211) U3.AE14(VSS_212) U3.AE18(VSS_213) U3.AE22(VSS_214) U3.AE25(VSS_215) U3.AE32(VSS_216) U3.AF3(VSS_217) U3.AF7(VSS_218) U3.AF28(VSS_219) U3.AF32(VSS_220) U3.AG3(VSS_221) U3.AG7(VSS_222) U3.AG32(VSS_223) U3.AH3(VSS_224) U3.AH10(VSS_225) U3.AH12(VSS_226) U3.AH16(VSS_227) U3.AH20(VSS_228) U3.AH25(VSS_229) U3.AH28(VSS_230) U3.AH29(VSS_231) U3.AH32(VSS_232) U3.AJ3(VSS_233) U3.AJ6(VSS_234) U3.AJ7(VSS_235) U3.AJ12(VSS_236) U3.AJ13(VSS_237) U3.AJ15(VSS_238) U3.AJ19(VSS_239) U3.AJ22(VSS_240) U3.AJ25(VSS_241) U3.AJ28(VSS_242) U3.AJ29(VSS_243) U3.AJ32(VSS_244) U3.AK3(VSS_245) U3.AK6(VSS_246) U3.AK31(VSS_247) U3.AK32(VSS_248) U3.AK33(VSS_249) U3.AK34(VSS_250) U3.AL1(VSS_251) U3.AL2(VSS_252) U3.AL3(VSS_253) U3.AL4(VSS_254) U3.AL5(VSS_255) U3.AL6(VSS_256) U3.AL31(VSS_257) U3.AM3(VSS_258) U3.AM6(VSS_259) U3.AM7(VSS_260) U3.AM8(VSS_261) U3.AM9(VSS_262) U3.AM10(VSS_263) U3.AM11(VSS_264) U3.AM12(VSS_265) U3.AM13(VSS_266) U3.AM14(VSS_267) U3.AM15(VSS_268) U3.AM16(VSS_269) U3.AM17(VSS_270) U3.AM18(VSS_271) U3.AM19(VSS_272) U3.AM20(VSS_273) U3.AM21(VSS_274) U3.AM22(VSS_275) U3.AM23(VSS_276) U3.AM24(VSS_277) U3.AM25(VSS_278) U3.AM26(VSS_279) U3.AM27(VSS_280) U3.AM28(VSS_281) U3.AM29(VSS_282) U3.AM30(VSS_283) U3.AM31(VSS_284) U3.AN1(VSS_285) U3.AN2(VSS_286) U3.AN6(VSS_287) U3.AN31(VSS_288) U3.AP1(VSS_289) U3.AP6(VSS_290) U3.AP31(VSS_291) U3.AP34(VSS_292) U3.B4(VSS_5) U3.B29(VSS_6) U3.C4(VSS_7) U3.C5(VSS_8) U3.C6(VSS_9) U3.C7(VSS_10) U3.C8(VSS_11) U3.C9(VSS_12) U3.C10(VSS_13) U3.C11(VSS_14) U3.C12(VSS_15) U3.C13(VSS_16) U3.C14(VSS_17) U3.C15(VSS_18) U3.C16(VSS_19) U3.C17(VSS_20) U3.C18(VSS_21) U3.C19(VSS_22) U3.C20(VSS_23) U3.C21(VSS_24) U3.C22(VSS_25) U3.C23(VSS_26) U3.C24(VSS_27) U3.C25(VSS_28) U3.C26(VSS_29) U3.C27(VSS_30) U3.C28(VSS_31) U3.C29(VSS_32) U3.D4(VSS_33) U3.D29(VSS_34) U3.D30(VSS_35) U3.D31(VSS_36) U3.D32(VSS_37) U3.D33(VSS_38) U3.D34(VSS_39) U3.E1(VSS_40) U3.E2(VSS_41) U3.E3(VSS_42) U3.E4(VSS_43) U3.E29(VSS_44) U3.E32(VSS_45) U3.F3(VSS_46) U3.F6(VSS_47) U3.F7(VSS_48) U3.F12(VSS_49) U3.F15(VSS_50) U3.F20(VSS_51) U3.F21(VSS_52) U3.F22(VSS_53) U3.F23(VSS_54) U3.F28(VSS_55) U3.F29(VSS_56) U3.F32(VSS_57) U3.G3(VSS_58) U3.G6(VSS_59) U3.G12(VSS_60) U3.G17(VSS_61) U3.G32(VSS_62) U3.H3(VSS_63) U3.H27(VSS_64) U3.H28(VSS_65) U3.H32(VSS_66) U3.J3(VSS_67) U3.J32(VSS_68) U3.K3(VSS_69) U3.K7(VSS_70) U3.K10(VSS_71) U3.K15(VSS_72) U3.K19(VSS_73) U3.K22(VSS_74) U3.K25(VSS_75) U3.K28(VSS_76) U3.K32(VSS_77) U3.L3(VSS_78) U3.L9(VSS_79) U3.L11(VSS_80) U3.L13(VSS_81) U3.L17(VSS_82) U3.L22(VSS_83) U3.L24(VSS_84) U3.L26(VSS_85) U3.L32(VSS_86) U3.M3(VSS_87) U3.M32(VSS_88) U3.N3(VSS_89) U3.N6(VSS_90) U3.N12(VSS_91) U3.N14(VSS_92) U3.N16(VSS_93) U3.N18(VSS_94) U3.N22(VSS_95) U3.N24(VSS_96) U3.N26(VSS_97) U3.N29(VSS_98) U3.N32(VSS_99) U3.P3(VSS_100) U3.P9(VSS_101) U3.P11(VSS_102) U3.P13(VSS_103) U3.P17(VSS_104) U3.P19(VSS_105) U3.P21(VSS_106) U3.P23(VSS_107) U3.P28(VSS_108) U3.P32(VSS_109) U3.R3(VSS_110) U3.R10(VSS_111) U3.R12(VSS_112) U3.R14(VSS_113) U3.R16(VSS_114) U3.R18(VSS_115) U3.R22(VSS_116) U3.R24(VSS_117) U3.R26(VSS_118) U3.R32(VSS_119) U3.T3(VSS_120) U3.T9(VSS_121) U3.T11(VSS_122) U3.T13(VSS_123) U3.T15(VSS_124) U3.T17(VSS_125) U3.T19(VSS_126) U3.T21(VSS_127) U3.T23(VSS_128) U3.T25(VSS_129) U3.T32(VSS_130) U3.U3(VSS_131) U3.U6(VSS_132) U3.U10(VSS_133) U3.U12(VSS_134) U3.U14(VSS_135) U3.U16(VSS_136) U3.U18(VSS_137) U3.U20(VSS_138) U3.U22(VSS_139) U3.U24(VSS_140) U3.U26(VSS_141) U3.U32(VSS_142) U3.V3(VSS_143) U3.V9(VSS_144) U3.V11(VSS_145) U3.V13(VSS_146) U3.V15(VSS_147) U3.V17(VSS_148) U3.V19(VSS_149) U3.V21(VSS_150) U3.V23(VSS_151) U3.V25(VSS_152) U3.V28(VSS_153) U3.V29(VSS_154) U3.V32(VSS_155) U3.W3(VSS_156) U3.W10(VSS_157) U3.W12(VSS_158) U3.W14(VSS_159) U3.W16(VSS_160) U3.W18(VSS_161) U3.W20(VSS_162) U3.W22(VSS_163) U3.W24(VSS_164) U3.W26(VSS_165) U3.W32(VSS_166) U3.Y3(VSS_167) U3.Y9(VSS_168) U3.Y11(VSS_169) U3.Y13(VSS_170) U3.Y17(VSS_171) U3.Y19(VSS_172) U3.Y21(VSS_173) U3.Y23(VSS_174) U3.Y25(VSS_175) U3.Y32(VSS_176) U4.4(VSS) ; also on sheet 3 4 5 6 7 8 9 10 11 12 13 14 15 16 17 18 27 28 29 30 31 32 33 34 35 36 37 38 39 40 41 42 43 44 45 46 47 48 49 50 51 52 53 54 55 56 57 58 59 60 61 62 63 64 65 66 67
P0V9A_PLX2: C334.1 C335.1 C336.1 C337.1 C338.1 C339.1 C340.1 C341.1 C342.1 C343.1 C344.1 C345.1 C346.1 C347.1 C348.1 C349.1 C350.1 C351.1 C352.1 C353.1 C354.1 C355.1 C356.1 C357.1 C358.1 C359.1 C360.1 C361.1 C362.1 C363.1 C364.1 C365.1 C366.1 C367.1 C368.1 C369.1 C370.1 C371.1 C372.1 C373.1 C374.1 C375.1 C376.1 C377.1 C378.1 C379.1 C380.1 C381.1 C382.1 C383.1 C384.1 C385.1 C386.1 C387.1 C388.1 C389.1 C390.1 C391.1 C392.1 C393.1 C394.1 C395.1 C396.1 C397.1 C398.1 C399.1 C400.1 C401.1 C402.1 C403.1 C404.1 C405.1 C406.1 C407.1 C408.1 C409.1 C410.1 C411.1 C412.1 C1404.1 C1405.1 C1406.1 C1407.1 U3.AA10(VDD09A_37) U3.AA15(VDD09A_38) U3.AA20(VDD09A_39) U3.AA25(VDD09A_40) U3.AB10(VDD09A_41) U3.AB15(VDD09A_42) U3.AB20(VDD09A_43) U3.AB25(VDD09A_44) U3.AC10(VDD09A_45) U3.AC11(VDD09A_46) U3.AC12(VDD09A_47) U3.AC13(VDD09A_48) U3.AC14(VDD09A_49) U3.AC15(VDD09A_50) U3.AC16(VDD09A_51) U3.AC17(VDD09A_52) U3.AC18(VDD09A_53) U3.AC19(VDD09A_54) U3.AC20(VDD09A_55) U3.AC21(VDD09A_56) U3.AC22(VDD09A_57) U3.AC23(VDD09A_58) U3.AC24(VDD09A_59) U3.AC25(VDD09A_60) U3.AD10(VDD09A_61) U3.AD14(VDD09A_62) U3.AD16(VDD09A_63) U3.AD19(VDD09A_64) U3.AD21(VDD09A_65) U3.AD25(VDD09A_66) U3.L10(VDD09A_1) U3.L14(VDD09A_2) U3.L16(VDD09A_3) U3.L19(VDD09A_4) U3.L21(VDD09A_5) U3.L25(VDD09A_6) U3.M10(VDD09A_7) U3.M11(VDD09A_8) U3.M12(VDD09A_9) U3.M13(VDD09A_10) U3.M14(VDD09A_11) U3.M15(VDD09A_12) U3.M16(VDD09A_13) U3.M17(VDD09A_14) U3.M18(VDD09A_15) U3.M19(VDD09A_16) U3.M20(VDD09A_17) U3.M21(VDD09A_18) U3.M22(VDD09A_19) U3.M23(VDD09A_20) U3.M24(VDD09A_21) U3.M25(VDD09A_22) U3.N10(VDD09A_23) U3.N15(VDD09A_24) U3.N20(VDD09A_25) U3.N25(VDD09A_26) U3.P10(VDD09A_27) U3.P15(VDD09A_28) U3.P20(VDD09A_29) U3.P25(VDD09A_30) U3.R15(VDD09A_31) U3.R20(VDD09A_32) U3.R25(VDD09A_33) U3.Y10(VDD09A_34) U3.Y15(VDD09A_35) U3.Y20(VDD09A_36) ; also on sheet 51 65
P0V9D_PLX2: C253.1 C254.1 C255.1 C256.1 C257.1 C258.1 C259.1 C260.1 C261.1 C262.1 C263.1 C264.1 C265.1 C266.1 C267.1 C268.1 C269.1 C270.1 C271.1 C272.1 C273.1 C274.1 C275.1 C276.1 C277.1 C278.1 C279.1 C280.1 C281.1 C282.1 C283.1 C284.1 C285.1 C286.1 C287.1 C288.1 C289.1 C290.1 C291.1 C292.1 C293.1 C294.1 C295.1 C296.1 C297.1 C298.1 C299.1 C300.1 C301.1 C302.1 C303.1 C304.1 C305.1 C306.1 C307.1 C308.1 C309.1 C310.1 C311.1 C312.1 C313.1 C314.1 C315.1 C316.1 C317.1 C318.1 C319.1 C320.1 C321.1 C322.1 C323.1 C324.1 C325.1 C326.1 C327.1 C328.1 C329.1 C330.1 C331.1 C332.1 C333.1 C1400.1 C1401.1 C1402.1 C1403.1 U3.AA11(VDD09_57) U3.AA13(VDD09_58) U3.AA17(VDD09_59) U3.AA19(VDD09_60) U3.AA21(VDD09_61) U3.AA23(VDD09_62) U3.AB12(VDD09_63) U3.AB14(VDD09_64) U3.AB16(VDD09_65) U3.AB18(VDD09_66) U3.AB22(VDD09_67) U3.AB24(VDD09_68) U3.N11(VDD09_1) U3.N13(VDD09_2) U3.N17(VDD09_3) U3.N19(VDD09_4) U3.N21(VDD09_5) U3.N23(VDD09_6) U3.P12(VDD09_7) U3.P14(VDD09_8) U3.P16(VDD09_9) U3.P18(VDD09_10) U3.P22(VDD09_11) U3.P24(VDD09_12) U3.R11(VDD09_13) U3.R13(VDD09_14) U3.R17(VDD09_15) U3.R19(VDD09_16) U3.R21(VDD09_17) U3.R23(VDD09_18) U3.T10(VDD09_19) U3.T12(VDD09_20) U3.T14(VDD09_21) U3.T16(VDD09_22) U3.T18(VDD09_23) U3.T20(VDD09_24) U3.T22(VDD09_25) U3.T24(VDD09_26) U3.U11(VDD09_27) U3.U13(VDD09_28) U3.U15(VDD09_29) U3.U17(VDD09_30) U3.U19(VDD09_31) U3.U21(VDD09_32) U3.U23(VDD09_33) U3.U25(VDD09_34) U3.V10(VDD09_35) U3.V12(VDD09_36) U3.V14(VDD09_37) U3.V16(VDD09_38) U3.V18(VDD09_39) U3.V20(VDD09_40) U3.V22(VDD09_41) U3.V24(VDD09_42) U3.W11(VDD09_43) U3.W13(VDD09_44) U3.W15(VDD09_45) U3.W17(VDD09_46) U3.W19(VDD09_47) U3.W21(VDD09_48) U3.W23(VDD09_49) U3.W25(VDD09_50) U3.Y12(VDD09_52) U3.Y14(VDD09_51) U3.Y16(VDD09_53) U3.Y18(VDD09_54) U3.Y22(VDD09_55) U3.Y24(VDD09_56) ; also on sheet 51 63
P1V8A_PLX2: C231.1 C232.1 C233.1 C234.1 C235.1 C236.1 C237.1 C238.1 C239.1 C240.1 C241.1 C242.1 C243.1 C244.1 C245.1 C246.1 C247.1 C248.1 C249.1 C250.1 C251.1 C252.1 R264.2 R265.2 U3.AA9(VDD18A_8) U3.AB26(VDD18A_9) U3.AD12(VDD18A_10) U3.AD15(VDD18A_11) U3.AD18(VDD18A_12) U3.AD20(VDD18A_13) U3.AD23(VDD18A_14) U3.L12(VDD18A_1) U3.L15(VDD18A_2) U3.L18(VDD18A_3) U3.L20(VDD18A_4) U3.L23(VDD18A_5) U3.N9(VDD18A_6) U3.P26(VDD18A_7) ; also on sheet 61
P1V8D_PLX2: C207.1 C208.1 C209.1 C210.1 C211.1 C212.1 C213.1 C214.1 C215.1 C216.1 C217.1 C218.1 C219.1 C220.1 C221.1 C222.1 C223.1 C224.1 C225.1 C226.1 C227.1 C228.1 C229.1 C230.1 R249.2 R251.1 R252.1 R253.1 R254.1 R261.1 R263.2 R266.1 R267.1 R268.1 R272.1 R273.1 R274.1 R275.1 R285.2 R286.1 R288.2 R290.2 R291.2 R292.2 R294.1 R295.2 R301.1 R303.2 R305.1 R307.1 R309.2 R312.2 R324.1 R325.1 R326.1 R333.2 R353.2 R355.2 R356.2 R359.2 R361.2 R363.2 R364.2 R367.2 R369.2 R371.2 R373.2 R375.2 R377.2 R379.2 R381.2 R383.2 R385.2 R387.2 U3.AG8(VDD18_11) U3.AG15(VDD18_12) U3.AG22(VDD18_13) U3.AG28(VDD18_14) U3.J9(VDD18_1) U3.J15(VDD18_2) U3.J21(VDD18_3) U3.J26(VDD18_4) U3.R9(VDD18_5) U3.T26(VDD18_6) U3.U9(VDD18_7) U3.V26(VDD18_8) U3.W9(VDD18_9) U3.Y26(VDD18_10) U4.8(VCC) ; also on sheet 46 51 61
P3V3: R270.1 R271.1 R277.1 R278.1 R279.1 R280.1 R281.1 R282.1 R283.1 R284.1 R1168.1 R1169.1 R1175.1 R1176.1 ; also on sheet 10 27 28 31 32 33 34 35 36 37 38 41 44 51 53 59 60 61 62 63 64 65 66
PEX_PE5_RXN0: U3.V31(PEX_PERN79) ; also on sheet 36
PEX_PE5_RXN1: U3.W31(PEX_PERN78) ; also on sheet 36
PEX_PE5_RXN2: U3.Y31(PEX_PERN77) ; also on sheet 36
PEX_PE5_RXN3: U3.AA31(PEX_PERN76) ; also on sheet 36
PEX_PE5_RXN4: U3.AB31(PEX_PERN75) ; also on sheet 36
PEX_PE5_RXN5: U3.AC31(PEX_PERN74) ; also on sheet 36
PEX_PE5_RXN6: U3.AD31(PEX_PERN73) ; also on sheet 36
PEX_PE5_RXN7: U3.AE31(PEX_PERN72) ; also on sheet 36
PEX_PE5_RXN8: U3.AF31(PEX_PERN71) ; also on sheet 36
PEX_PE5_RXN9: U3.AG31(PEX_PERN70) ; also on sheet 36
PEX_PE5_RXN10: U3.AH31(PEX_PERN69) ; also on sheet 36
PEX_PE5_RXN11: U3.AJ31(PEX_PERN68) ; also on sheet 36
PEX_PE5_RXN12: U3.AL30(PEX_PERN67) ; also on sheet 36
PEX_PE5_RXN13: U3.AL29(PEX_PERN66) ; also on sheet 36
PEX_PE5_RXN14: U3.AL28(PEX_PERN65) ; also on sheet 36
PEX_PE5_RXN15: U3.AL27(PEX_PERN64) ; also on sheet 36
PEX_PE5_RXP0: U3.V30(PEX_PERP79) ; also on sheet 36
PEX_PE5_RXP1: U3.W30(PEX_PERP78) ; also on sheet 36
PEX_PE5_RXP2: U3.Y30(PEX_PERP77) ; also on sheet 36
PEX_PE5_RXP3: U3.AA30(PEX_PERP76) ; also on sheet 36
PEX_PE5_RXP4: U3.AB30(PEX_PERP75) ; also on sheet 36
PEX_PE5_RXP5: U3.AC30(PEX_PERP74) ; also on sheet 36
PEX_PE5_RXP6: U3.AD30(PEX_PERP73) ; also on sheet 36
PEX_PE5_RXP7: U3.AE30(PEX_PERP72) ; also on sheet 36
PEX_PE5_RXP8: U3.AF30(PEX_PERP71) ; also on sheet 36
PEX_PE5_RXP9: U3.AG30(PEX_PERP70) ; also on sheet 36
PEX_PE5_RXP10: U3.AH30(PEX_PERP69) ; also on sheet 36
PEX_PE5_RXP11: U3.AJ30(PEX_PERP68) ; also on sheet 36
PEX_PE5_RXP12: U3.AK30(PEX_PERP67) ; also on sheet 36
PEX_PE5_RXP13: U3.AK29(PEX_PERP66) ; also on sheet 36
PEX_PE5_RXP14: U3.AK28(PEX_PERP65) ; also on sheet 36
PEX_PE5_RXP15: U3.AK27(PEX_PERP64) ; also on sheet 36
PEX_PE5_TXN0: U3.V34(PEX_PETN79) ; also on sheet 36
PEX_PE5_TXN1: U3.W34(PEX_PETN78) ; also on sheet 36
PEX_PE5_TXN2: U3.Y34(PEX_PETN77) ; also on sheet 36
PEX_PE5_TXN3: U3.AA34(PEX_PETN76) ; also on sheet 36
PEX_PE5_TXN4: U3.AB34(PEX_PETN75) ; also on sheet 36
PEX_PE5_TXN5: U3.AC34(PEX_PETN74) ; also on sheet 36
PEX_PE5_TXN6: U3.AD34(PEX_PETN73) ; also on sheet 36
PEX_PE5_TXN7: U3.AE34(PEX_PETN72) ; also on sheet 36
PEX_PE5_TXN8: U3.AF34(PEX_PETN71) ; also on sheet 36
PEX_PE5_TXN9: U3.AG34(PEX_PETN70) ; also on sheet 36
PEX_PE5_TXN10: U3.AH34(PEX_PETN69) ; also on sheet 36
PEX_PE5_TXN11: U3.AJ34(PEX_PETN68) ; also on sheet 36
PEX_PE5_TXN12: U3.AP30(PEX_PETN67) ; also on sheet 36
PEX_PE5_TXN13: U3.AP29(PEX_PETN66) ; also on sheet 36
PEX_PE5_TXN14: U3.AP28(PEX_PETN65) ; also on sheet 36
PEX_PE5_TXN15: U3.AP27(PEX_PETN64) ; also on sheet 36
PEX_PE5_TXP0: U3.V33(PEX_PETP79) ; also on sheet 36
PEX_PE5_TXP1: U3.W33(PEX_PETP78) ; also on sheet 36
PEX_PE5_TXP2: U3.Y33(PEX_PETP77) ; also on sheet 36
PEX_PE5_TXP3: U3.AA33(PEX_PETP76) ; also on sheet 36
PEX_PE5_TXP4: U3.AB33(PEX_PETP75) ; also on sheet 36
PEX_PE5_TXP5: U3.AC33(PEX_PETP74) ; also on sheet 36
PEX_PE5_TXP6: U3.AD33(PEX_PETP73) ; also on sheet 36
PEX_PE5_TXP7: U3.AE33(PEX_PETP72) ; also on sheet 36
PEX_PE5_TXP8: U3.AF33(PEX_PETP71) ; also on sheet 36
PEX_PE5_TXP9: U3.AG33(PEX_PETP70) ; also on sheet 36
PEX_PE5_TXP10: U3.AH33(PEX_PETP69) ; also on sheet 36
PEX_PE5_TXP11: U3.AJ33(PEX_PETP68) ; also on sheet 36
PEX_PE5_TXP12: U3.AN30(PEX_PETP67) ; also on sheet 36
PEX_PE5_TXP13: U3.AN29(PEX_PETP66) ; also on sheet 36
PEX_PE5_TXP14: U3.AN28(PEX_PETP65) ; also on sheet 36
PEX_PE5_TXP15: U3.AN27(PEX_PETP64) ; also on sheet 36
PEX_PE6_RXN0: U3.D25(PEX_PERN95) ; also on sheet 37
PEX_PE6_RXN1: U3.D26(PEX_PERN94) ; also on sheet 37
PEX_PE6_RXN2: U3.D27(PEX_PERN93) ; also on sheet 37
PEX_PE6_RXN3: U3.D28(PEX_PERN92) ; also on sheet 37
PEX_PE6_RXN4: U3.E31(PEX_PERN91) ; also on sheet 37
PEX_PE6_RXN5: U3.F31(PEX_PERN90) ; also on sheet 37
PEX_PE6_RXN6: U3.G31(PEX_PERN89) ; also on sheet 37
PEX_PE6_RXN7: U3.H31(PEX_PERN88) ; also on sheet 37
PEX_PE6_RXN8: U3.J31(PEX_PERN87) ; also on sheet 37
PEX_PE6_RXN9: U3.K31(PEX_PERN86) ; also on sheet 37
PEX_PE6_RXN10: U3.L31(PEX_PERN85) ; also on sheet 37
PEX_PE6_RXN11: U3.M31(PEX_PERN84) ; also on sheet 37
PEX_PE6_RXN12: U3.P31(PEX_PERN83) ; also on sheet 37
PEX_PE6_RXN13: U3.R31(PEX_PERN82) ; also on sheet 37
PEX_PE6_RXN14: U3.T31(PEX_PERN81) ; also on sheet 37
PEX_PE6_RXN15: U3.U31(PEX_PERN80) ; also on sheet 37
PEX_PE6_RXP0: U3.E25(PEX_PERP95) ; also on sheet 37
PEX_PE6_RXP1: U3.E26(PEX_PERP94) ; also on sheet 37
PEX_PE6_RXP2: U3.E27(PEX_PERP93) ; also on sheet 37
PEX_PE6_RXP3: U3.E28(PEX_PERP92) ; also on sheet 37
PEX_PE6_RXP4: U3.E30(PEX_PERP91) ; also on sheet 37
PEX_PE6_RXP5: U3.F30(PEX_PERP90) ; also on sheet 37
PEX_PE6_RXP6: U3.G30(PEX_PERP89) ; also on sheet 37
PEX_PE6_RXP7: U3.H30(PEX_PERP88) ; also on sheet 37
PEX_PE6_RXP8: U3.J30(PEX_PERP87) ; also on sheet 37
PEX_PE6_RXP9: U3.K30(PEX_PERP86) ; also on sheet 37
PEX_PE6_RXP10: U3.L30(PEX_PERP85) ; also on sheet 37
PEX_PE6_RXP11: U3.M30(PEX_PERP84) ; also on sheet 37
PEX_PE6_RXP12: U3.P30(PEX_PERP83) ; also on sheet 37
PEX_PE6_RXP13: U3.R30(PEX_PERP82) ; also on sheet 37
PEX_PE6_RXP14: U3.T30(PEX_PERP81) ; also on sheet 37
PEX_PE6_RXP15: U3.U30(PEX_PERP80) ; also on sheet 37
PEX_PE6_TXN0: U3.A25(PEX_PETN95) ; also on sheet 37
PEX_PE6_TXN1: U3.A26(PEX_PETN94) ; also on sheet 37
PEX_PE6_TXN2: U3.A27(PEX_PETN93) ; also on sheet 37
PEX_PE6_TXN3: U3.A28(PEX_PETN92) ; also on sheet 37
PEX_PE6_TXN4: U3.E34(PEX_PETN91) ; also on sheet 37
PEX_PE6_TXN5: U3.F34(PEX_PETN90) ; also on sheet 37
PEX_PE6_TXN6: U3.G34(PEX_PETN89) ; also on sheet 37
PEX_PE6_TXN7: U3.H34(PEX_PETN88) ; also on sheet 37
PEX_PE6_TXN8: U3.J34(PEX_PETN87) ; also on sheet 37
PEX_PE6_TXN9: U3.K34(PEX_PETN86) ; also on sheet 37
PEX_PE6_TXN10: U3.L34(PEX_PETN85) ; also on sheet 37
PEX_PE6_TXN11: U3.M34(PEX_PETN84) ; also on sheet 37
PEX_PE6_TXN12: U3.P34(PEX_PETN83) ; also on sheet 37
PEX_PE6_TXN13: U3.R34(PEX_PETN82) ; also on sheet 37
PEX_PE6_TXN14: U3.T34(PEX_PETN81) ; also on sheet 37
PEX_PE6_TXN15: U3.U34(PEX_PETN80) ; also on sheet 37
PEX_PE6_TXP0: U3.B25(PEX_PETP95) ; also on sheet 37
PEX_PE6_TXP1: U3.B26(PEX_PETP94) ; also on sheet 37
PEX_PE6_TXP2: U3.B27(PEX_PETP93) ; also on sheet 37
PEX_PE6_TXP3: U3.B28(PEX_PETP92) ; also on sheet 37
PEX_PE6_TXP4: U3.E33(PEX_PETP91) ; also on sheet 37
PEX_PE6_TXP5: U3.F33(PEX_PETP90) ; also on sheet 37
PEX_PE6_TXP6: U3.G33(PEX_PETP89) ; also on sheet 37
PEX_PE6_TXP7: U3.H33(PEX_PETP88) ; also on sheet 37
PEX_PE6_TXP8: U3.J33(PEX_PETP87) ; also on sheet 37
PEX_PE6_TXP9: U3.K33(PEX_PETP86) ; also on sheet 37
PEX_PE6_TXP10: U3.L33(PEX_PETP85) ; also on sheet 37
PEX_PE6_TXP11: U3.M33(PEX_PETP84) ; also on sheet 37
PEX_PE6_TXP12: U3.P33(PEX_PETP83) ; also on sheet 37
PEX_PE6_TXP13: U3.R33(PEX_PETP82) ; also on sheet 37
PEX_PE6_TXP14: U3.T33(PEX_PETP81) ; also on sheet 37
PEX_PE6_TXP15: U3.U33(PEX_PETP80) ; also on sheet 37
PLX2_I2C_ADDR: R268.2 R269.1 U3.K11(I2C_ADDR)
PLX2_JTAG_TCK: R253.2 U3.AB7(JTAG_TCK)
PLX2_JTAG_TDI: R261.2 U3.D1(JTAG_TDI)
PLX2_JTAG_TMS: R251.2 U3.N8(JTAG_TMS)
PLX2_JTAG_TRST_N: R255.2 U3.P7(JTAG_TRST#)
PLX2_PORT_GOOD0_D_N: D6.2 Q11.3(D)
PLX2_PORT_GOOD0_G_N: Q11.1(G) Q12.3(D) R271.2
PLX2_PORT_GOOD0_N: Q12.1(G) U3.G13(PORT_GOOD0#_SHP_PERST0#_HP_PWREN_A)
PLX2_PORT_GOOD0_N_R: D6.1 R270.2
PLX2_PORT_GOOD4_D_N: D22.2 Q47.3(D)
PLX2_PORT_GOOD4_G_N: Q46.3(D) Q47.1(G) R1169.2
PLX2_PORT_GOOD4_N: Q46.1(G) U3.C3(PORT_GOOD4#_SHP_PERST4#_HP_PWREN_B)
PLX2_PORT_GOOD4_N_R: D22.1 R1168.2
PLX2_PORT_GOOD5_D_N: D24.2 Q51.3(D)
PLX2_PORT_GOOD5_G_N: Q50.3(D) Q51.1(G) R1176.2
PLX2_PORT_GOOD5_N: Q50.1(G) U3.K9(PORT_GOOD5#_SHP_PERST5#_HP_CLKEN_B#)
PLX2_PORT_GOOD5_N_R: D24.1 R1175.2
PLX2_PORT_GOOD8_D_N: D7.2 Q13.3(D)
PLX2_PORT_GOOD8_G_N: Q13.1(G) Q14.3(D) R278.2
PLX2_PORT_GOOD8_N: Q14.1(G) U3.AF24(PORT_GOOD8#_SHP_PERST8#_HP_PWREN_C)
PLX2_PORT_GOOD8_N_R: D7.1 R277.2
PLX2_PORT_GOOD12_D_N: D8.2 Q15.3(D)
PLX2_PORT_GOOD12_G_N: Q15.1(G) Q16.3(D) R280.2
PLX2_PORT_GOOD12_N: Q16.1(G) U3.G23(PORT_GOOD12#_SHP_PERST12#_HP_PWREN_D)
PLX2_PORT_GOOD12_N_R: D8.1 R279.2
PLX2_PORT_GOOD16_D_N: D9.2 Q17.3(D)
PLX2_PORT_GOOD16_G_N: Q17.1(G) Q18.3(D) R282.2
PLX2_PORT_GOOD16_N: Q18.1(G) U3.AC28(PORT_GOOD16#_SHP_PERST16#_HP_PWREN_E)
PLX2_PORT_GOOD16_N_R: D9.1 R281.2
PLX2_PORT_GOOD20_D_N: D10.2 Q19.3(D)
PLX2_PORT_GOOD20_G_N: Q19.1(G) Q20.3(D) R284.2
PLX2_PORT_GOOD20_N: Q20.1(G) U3.M26(PORT_GOOD20#_SHP_PERST20#_HP_PWREN_F)
PLX2_PORT_GOOD20_N_R: D10.1 R283.2
PLX2_REXT_A16: R238.2 U3.AJ27(REXT_A16)
PLX2_REXT_A17: R232.2 U3.AG29(REXT_A17)
PLX2_REXT_A18: R234.2 U3.AB29(REXT_A18)
PLX2_REXT_A19: R236.2 U3.Y29(REXT_A19)
PLX2_REXT_A20: R240.2 U3.U29(REXT_A20)
PLX2_REXT_A21: R242.2 U3.M29(REXT_A21)
PLX2_REXT_A22: R243.2 U3.H29(REXT_A22)
PLX2_REXT_A23: R244.2 U3.F27(REXT_A23)
PLX2_REXT_B16: R231.2 U3.AJ26(REXT_B16)
PLX2_REXT_B17: R233.2 U3.AF29(REXT_B17)
PLX2_REXT_B18: R235.2 U3.AA29(REXT_B18)
PLX2_REXT_B19: R237.2 U3.W29(REXT_B19)
PLX2_REXT_B20: R241.2 U3.T29(REXT_B20)
PLX2_REXT_B21: R247.2 U3.L29(REXT_B21)
PLX2_REXT_B22: R248.2 U3.G29(REXT_B22)
PLX2_REXT_B23: R245.2 U3.F26(REXT_B23)
PLX2_REXT_CMU4: R239.2 U3.AE29(REXT_CMU4)
PLX2_REXT_CMU5: R246.2 U3.J29(REXT_CMU5)
PLX2_SPARE0: R263.1 U3.H15(SPARE0)
PLX2_SPARE1: R266.2 U3.J18(SPARE1)
PLX2_SPARE2: R267.2 U3.AE19(SPARE2)
PLX2_STRAP_GEN1_COMPLIANCE_N: R305.2 U3.K8(STRAP_GEN1_COMPLIANCE#)
PLX2_STRAP_GEN1_GEN2: R377.1 R378.1 U3.H17(STRAP_GEN1_GEN2)
PLX2_STRAP_HP_POLARITY_CTRL: R307.2 U3.AE15(STRAP_HP_POLARITY_CTRL)
PLX2_STRAP_I2C_SMBUS_CFG_EN_N: R301.2 U3.AN3(STRAP_I2C_SMBUS_CFG_EN#)
PLX2_STRAP_I2C_SMBUS_SEL: R383.1 R384.1 U3.AP4(STRAP_I2C_SMBUS_SEL)
PLX2_STRAP_MGMT_CFG_EN: R364.1 R366.1 U3.V8(STRAP_MGMT_CFG_EN)
PLX2_STRAP_NT0_UPSTRM_PORTSEL0: R285.1 R287.1 U3.N7(STRAP_NT0_UPSTRM_PORTSEL0)
PLX2_STRAP_NT0_UPSTRM_PORTSEL1: R291.1 R293.1 U3.C2(STRAP_NT0_UPSTRM_PORTSEL1)
PLX2_STRAP_NT0_UPSTRM_PORTSEL2: R295.1 R304.1 U3.AN5(STRAP_NT0_UPSTRM_PORTSEL2)
PLX2_STRAP_NT1_UPSTRM_PORTSEL0: R300.1 R309.1 U3.K16(STRAP_NT1_UPSTRM_PORTSEL0)
PLX2_STRAP_NT1_UPSTRM_PORTSEL1: R312.1 R314.1 U3.J13(STRAP_NT1_UPSTRM_PORTSEL1)
PLX2_STRAP_NT1_UPSTRM_PORTSEL2: R303.1 R318.1 U3.G15(STRAP_NT1_UPSTRM_PORTSEL2)
PLX2_STRAP_PLL_BYPASS_N: R324.2 U3.AF15(STRAP_PLL_BYPASS#)
PLX2_STRAP_PROBE_MODE_N: R325.2 U3.AE17(STRAP_PROBE_MODE#)
PLX2_STRAP_REFCLK_SSC_EN0: R327.2 U3.AH13(STRAP_REFCLK_SSC_EN0)
PLX2_STRAP_REFCLK_SSC_EN1: R328.2 U3.W8(STRAP_REFCLK_SSC_EN1)
PLX2_STRAP_REFCLK_SSC_EN2: R329.2 U3.AG19(STRAP_REFCLK_SSC_EN2)
PLX2_STRAP_REFCLK_SSC_EN3: R330.2 U3.AH19(STRAP_REFCLK_SSC_EN3)
PLX2_STRAP_REFCLK_SSC_EN4: R331.2 U3.M9(STRAP_REFCLK_SSC_EN4)
PLX2_STRAP_REFCLK_SSC_EN5: R332.2 U3.G16(STRAP_REFCLK_SSC_EN5)
PLX2_STRAP_REFCLK_SSC_EN6: R334.2 U3.P8(STRAP_REFCLK_SSC_EN6)
PLX2_STRAP_REFCLK_SSC_EN7: R336.2 U3.C1(STRAP_REFCLK_SSC_EN7)
PLX2_STRAP_REFCLK_SSC_EN8: R337.2 U3.AE26(STRAP_REFCLK_SSC_EN8)
PLX2_STRAP_REFCLK_SSC_EN9: R338.2 U3.AG20(STRAP_REFCLK_SSC_EN9)
PLX2_STRAP_REFCLK_SSC_EN10: R339.2 U3.AP32(STRAP_REFCLK_SSC_EN10)
PLX2_STRAP_REFCLK_SSC_EN11: R340.2 U3.AL33(STRAP_REFCLK_SSC_EN11)
PLX2_STRAP_REFCLK_SSC_EN12: R341.2 U3.J20(STRAP_REFCLK_SSC_EN12)
PLX2_STRAP_REFCLK_SSC_EN13: R342.2 U3.J24(STRAP_REFCLK_SSC_EN13)
PLX2_STRAP_REFCLK_SSC_EN14: R343.2 U3.G21(STRAP_REFCLK_SSC_EN14)
PLX2_STRAP_REFCLK_SSC_EN15: R344.2 U3.H21(STRAP_REFCLK_SSC_EN15)
PLX2_STRAP_REFCLK_SSC_EN16: R345.2 U3.Y28(STRAP_REFCLK_SSC_EN16)
PLX2_STRAP_REFCLK_SSC_EN17: R346.2 U3.AP33(STRAP_REFCLK_SSC_EN17)
PLX2_STRAP_REFCLK_SSC_EN18: R347.2 U3.V27(STRAP_REFCLK_SSC_EN18)
PLX2_STRAP_REFCLK_SSC_EN19: R348.2 U3.U28(STRAP_REFCLK_SSC_EN19)
PLX2_STRAP_REFCLK_SSC_EN20: R349.2 U3.J27(STRAP_REFCLK_SSC_EN20)
PLX2_STRAP_REFCLK_SSC_EN21: R350.2 U3.M28(STRAP_REFCLK_SSC_EN21)
PLX2_STRAP_REFCLK_SSC_EN22: R351.2 U3.C32(STRAP_REFCLK_SSC_EN22)
PLX2_STRAP_REFCLK_SSC_EN23: R352.2 U3.B31(STRAP_REFCLK_SSC_EN23)
PLX2_STRAP_RESERVED0: R288.1 R297.2 U3.AM4(STRAP_RESERVED0)
PLX2_STRAP_RESERVED1: R306.2 U3.AC8(STRAP_RESERVED1)
PLX2_STRAP_RESERVED2: R290.1 R298.2 U3.H8(STRAP_RESERVED2)
PLX2_STRAP_RESERVED3: R299.2 U3.AF12(STRAP_RESERVED3)
PLX2_STRAP_RESERVED4: R308.2 U3.M7(STRAP_RESERVED4)
PLX2_STRAP_RESERVED5: R310.2 U3.G9(STRAP_RESERVED5)
PLX2_STRAP_RESERVED6: R302.2 U3.AP5(STRAP_RESERVED6)
PLX2_STRAP_RESERVED7: R311.2 U3.AC9(STRAP_RESERVED7)
PLX2_STRAP_RESERVED8: R313.2 U3.AF19(STRAP_RESERVED8)
PLX2_STRAP_RESERVED9: R315.2 U3.AH18(STRAP_RESERVED9)
PLX2_STRAP_RESERVED10: R292.1 R316.2 U3.AF10(STRAP_RESERVED10)
PLX2_STRAP_RESERVED11: R317.2 U3.AD7(STRAP_RESERVED11)
PLX2_STRAP_RESERVED12: R319.2 U3.AN4(STRAP_RESERVED12)
PLX2_STRAP_RESERVED13: R320.2 U3.V7(STRAP_RESERVED13)
PLX2_STRAP_RESERVED14: R321.2 U3.AE16(STRAP_RESERVED14)
PLX2_STRAP_RESERVED15: R322.2 U3.AC7(STRAP_RESERVED15)
PLX2_STRAP_RESERVED17: R323.2 U3.H16(STRAP_RESERVED17)
PLX2_STRAP_SERDES_MODE_N: R326.2 U3.AG18(STRAP_SERDES_MODE_EN#)
PLX2_STRAP_STN0_PORTCFG0: R353.1 R354.1 U3.AD8(STRAP_STN0_PORTCFG0)
PLX2_STRAP_STN0_PORTCFG1: R355.1 R357.1 U3.AF11(STRAP_STN0_PORTCFG1)
PLX2_STRAP_STN1_PORTCFG0: R363.1 R365.1 U3.H12(STRAP_STN1_PORTCFG0)
PLX2_STRAP_STN1_PORTCFG1: R367.1 R368.1 U3.J10(STRAP_STN1_PORTCFG1)
PLX2_STRAP_STN2_PORTCFG0: R369.1 R370.1 U3.AE21(STRAP_STN2_PORTCFG0)
PLX2_STRAP_STN2_PORTCFG1: R371.1 R372.1 U3.AF23(STRAP_STN2_PORTCFG1)
PLX2_STRAP_STN3_PORTCFG0: R373.1 R374.1 U3.K23(STRAP_STN3_PORTCFG0)
PLX2_STRAP_STN3_PORTCFG1: R375.1 R376.1 U3.G25(STRAP_STN3_PORTCFG1)
PLX2_STRAP_STN4_PORTCFG0: R379.1 R380.1 U3.AD26(STRAP_STN4_PORTCFG0)
PLX2_STRAP_STN4_PORTCFG1: R381.1 R382.1 U3.N28(STRAP_STN4_PORTCFG1)
PLX2_STRAP_STN5_PORTCFG0: R385.1 R386.1 U3.J28(STRAP_STN5_PORTCFG0)
PLX2_STRAP_STN5_PORTCFG1: R387.1 R388.1 U3.K26(STRAP_STN5_PORTCFG1)
PLX2_STRAP_TESTMODE: R333.1 R335.1 U3.H13(STRAP_TESTMODE)
PLX2_STRAP_VS0_UPSTRM_PORTSEL0: R356.1 R358.1 U3.AE13(STRAP_VS0_UPSTRM_PORTSEL0)
PLX2_STRAP_VS0_UPSTRM_PORTSEL1: R359.1 R360.1 U3.H10(STRAP_VS0_UPSTRM_PORTSEL1)
PLX2_STRAP_VS0_UPSTRM_PORTSEL2: R361.1 R362.1 U3.K18(STRAP_VS0_UPSTRM_PORTSEL2)
PLX2_STRAP_VS_MODE0: R286.2 R289.2 U3.AB8(STRAP_VS_MODE0)
PLX2_STRAP_VS_MODE1: R294.2 R296.2 U3.AF16(STRAP_VS_MODE1)
PLX2_THERMAL_SENSE0: R264.1 U3.B30(VDD18A_THERMAL_SENSE0)
PLX2_THERMAL_SENSE1: R265.1 U3.AN32(VDD18A_THERMAL_SENSE1)
RST_PLX2_N: R250.1 ; also on sheet 55
RST_PLX2_PERST_N: R249.1 R250.2 U3.AG10(PEX_PERST#)
SMB_PLX2_SCL: R262.2 ; also on sheet 46
SMB_PLX2_SCL_R: R252.2 R262.1 U3.R8(I2C_SCL0)
SMB_PLX2_SDA: R257.2 ; also on sheet 46
SMB_PLX2_SDA_R: R254.2 R257.1 U3.R7(I2C_SDA0)
SPI_PLX2_CS_N: R258.1 R272.2 U4.1(S#)
SPI_PLX2_CS_N_R: R258.2 U3.AG14(EE_CS#)
SPI_PLX2_DI: R259.1 U4.5(D)
SPI_PLX2_DI_R: R259.2 U3.J11(EE_DI)
SPI_PLX2_DO: R260.1 R273.2 U4.2(Q)
SPI_PLX2_DO_R: R260.2 U3.AA8(EE_DO)
SPI_PLX2_HOLD_N: R275.2 U4.7(HOLD#)
SPI_PLX2_SK: R256.1 U4.6(C)
SPI_PLX2_SK_R: R256.2 U3.AM5(EE_SK)
SPI_PLX2_WP_N: R274.2 R276.1 U4.3(W#)
TP_PLX2_GPIO0: U3.AH14(GPIO0_HP_MRL_A#)
TP_PLX2_GPIO1: U3.AF8(GPIO1_HP_PWRFLT_A#)
TP_PLX2_GPIO2: U3.AE11(GPIO2_HP_BUTTON_A#)
TP_PLX2_GPIO3: U3.AG12(GPIO3_HP_PWR_GOOD_A)
TP_PLX2_GPIO4: U3.AE9(GPIO4_HP_PRSNT_A#)
TP_PLX2_GPIO5: U3.AF18(GPIO5_HP_ATNLED_A#)
TP_PLX2_GPIO6: U3.B2(GPIO6_HP_MRL_B#)
TP_PLX2_GPIO7: U3.K13(GPIO7_HP_PWRFLT_B#)
TP_PLX2_GPIO8: U3.G10(GPIO8_HP_BUTTON_B#)
TP_PLX2_GPIO9: U3.G8(GPIO9_HP_PWR_GOOD_B)
TP_PLX2_GPIO10: U3.J12(GPIO10_HP_PRSNT_B#)
TP_PLX2_GPIO11: U3.A3(GPIO11_HP_ATNLED_B#)
TP_PLX2_GPIO12: U3.AF27(GPIO12_HP_MRL_C#)
TP_PLX2_GPIO13: U3.AF21(GPIO13_HP_PWRFLT_C#)
TP_PLX2_GPIO14: U3.AF22(GPIO14_HP_BUTTON_C#)
TP_PLX2_GPIO15: U3.AE23(GPIO15_HP_PWR_GOOD_C)
TP_PLX2_GPIO16: U3.AH22(GPIO16_HP_PRSNT_C#)
TP_PLX2_GPIO17: U3.AF26(GPIO17_HP_ATNLED_C#)
TP_PLX2_GPIO18: U3.J19(GPIO18_HP_MRL_D#)
TP_PLX2_GPIO19: U3.H25(GPIO19_HP_PWRFLT_D#)
TP_PLX2_GPIO20: U3.K21(GPIO20_HP_BUTTON_D#)
TP_PLX2_GPIO21: U3.H24(GPIO21_HP_PWR_GOOD_D)
TP_PLX2_GPIO22: U3.J23(GPIO22_HP_PRSNT_D#)
TP_PLX2_GPIO23: U3.K17(GPIO23_HP_ATNLED_D#)
TP_PLX2_GPIO24: U3.T28(GPIO24_HP_MRL_E#)
TP_PLX2_GPIO25: U3.AL34(GPIO25_HP_PWRFLT_E#)
TP_PLX2_GPIO26: U3.AD27(GPIO26_HP_BUTTON_E#)
TP_PLX2_GPIO27: U3.AM34(GPIO27_HP_PWR_GOOD_E)
TP_PLX2_GPIO28: U3.AN33(GPIO28_HP_PRSNT_E#)
TP_PLX2_GPIO29: U3.AA27(GPIO29_HP_ATNLED_E#)
TP_PLX2_GPIO30: U3.C31(GPIO30_HP_MRL_F#)
TP_PLX2_GPIO31: U3.B34(GPIO31_HP_PWRFLT_F#)
TP_PLX2_GPIO32: U3.K27(GPIO32_HP_BUTTON_F#)
TP_PLX2_GPIO33: U3.B33(GPIO33_HP_PWR_GOOD_F)
TP_PLX2_GPIO34: U3.M27(GPIO34_HP_PRSNT_F#)
TP_PLX2_GPIO35: U3.C33(GPIO35_HP_ATNLED_F#)
TP_PLX2_JTAG_TDO: U3.AF13(JTAG_TDO)
TP_PLX2_PORT_GOOD1_N: U3.AH15(PORT_GOOD1#_SHP_PERST1#_HP_CLKEN_A#)
TP_PLX2_PORT_GOOD2_N: U3.AG16(PORT_GOOD2#_SHP_PERST2#_HP_PERST_A#)
TP_PLX2_PORT_GOOD3_N: U3.AG13(PORT_GOOD3#_SHP_PERST3#_HP_PWRLED_A#)
TP_PLX2_PORT_GOOD6_N: U3.D3(PORT_GOOD6#_SHP_PERST6#_HP_PERST_B#)
TP_PLX2_PORT_GOOD7_N: U3.H9(PORT_GOOD7#_SHP_PERST7#_HP_PWRLED_B#)
TP_PLX2_PORT_GOOD9_N: U3.AE24(PORT_GOOD9#_SHP_PERST9#_HP_CLKEN_C#)
TP_PLX2_PORT_GOOD10_N: U3.AF25(PORT_GOOD10#_SHP_PERST10#_HP_PERST_C#)
TP_PLX2_PORT_GOOD11_N: U3.AH23(PORT_GOOD11#_SHP_PERST11#_HP_PWRLED_C#)
TP_PLX2_PORT_GOOD13_N: U3.H20(PORT_GOOD13#_SHP_PERST13#_HP_CLKEN_D#)
TP_PLX2_PORT_GOOD14_N: U3.H19(PORT_GOOD14#_SHP_PERST14#_HP_PERST_D#)
TP_PLX2_PORT_GOOD15_N: U3.H23(PORT_GOOD15#_SHP_PERST15#_HP_PWRLED_D#)
TP_PLX2_PORT_GOOD17_N: U3.AM33(PORT_GOOD17#_SHP_PERST17#_HP_CLKEN_E#)
TP_PLX2_PORT_GOOD18_N: U3.AN34(PORT_GOOD18#_SHP_PERST18#_HP_PERST_E#)
TP_PLX2_PORT_GOOD19_N: U3.AD28(PORT_GOOD19#_SHP_PERST19#_HP_PWRLED_E#)
TP_PLX2_PORT_GOOD21_N: U3.A32(PORT_GOOD21#_SHP_PERST21#_HP_CLKEN_F#)
TP_PLX2_PORT_GOOD22_N: U3.C30(PORT_GOOD22#_SHP_PERST22#_HP_PERST_F#)
TP_PLX2_PORT_GOOD23_N: U3.C34(PORT_GOOD23#_SHP_PERST23#_HP_PWRLED_F#)
TP_PLX2_SHPC_INT_N: U3.AF9(SHPC_INT#)
TP_PLX2_VS0_FATAL_ERR_N: U3.U8(VS0_FATAL_ERR#)
TP_PLX2_VS0_PERST_N: U3.K12(VS0_PERST#)
TP_PLX2_VS0_PEX_INTA_N: U3.J14(VS0_PEX_INTA#)
TP_PLX2_VS1_FATAL_ERR_N: U3.J17(VS1_FATAL_ERR#)
TP_PLX2_VS1_PERST_N: U3.B3(VS1_PERST#)
TP_PLX2_VS1_PEX_INTA_N: U3.B1(VS1_PEX_INTA#)
TP_PLX2_VS2_FATAL_ERR_N: U3.AE20(VS2_FATAL_ERR#)
TP_PLX2_VS2_PERST_N: U3.AG23(VS2_PERST#)
TP_PLX2_VS2_PEX_INTA_N: U3.AG25(VS2_PEX_INTA#)
TP_PLX2_VS3_FATAL_ERR_N: U3.A31(VS3_FATAL_ERR#)
TP_PLX2_VS3_PERST_N: U3.J22(VS3_PERST#)
TP_PLX2_VS3_PEX_INTA_N: U3.G24(VS3_PEX_INTA#)
TP_RST_PLX2_NT0_PERST_N: U3.AP2(PEX_NT0_PERST#)
TP_RST_PLX2_NT1_PERST_N: U3.K14(PEX_NT1_PERST#)
TP_SMB_PLX2_I2C_SCL1_R: U3.AE12(I2C_SCL1)
TP_SMB_PLX2_I2C_SDA1_R: U3.AP3(I2C_SDA1)

Not connected (* = marked no-connect by the designer): U3 AB4(NC32) AB5(NC33) AB27(PEX_REFCLK_SSCP18) AB28(PEX_REFCLK_SSCN18) AC6(NC34) AC27(NC35) AD29(NC36) AE27(PEX_REFCLK_SSCP17) AE28(PEX_REFCLK_SSCN17) AF14(NC37) AF17(NC38) AF20(NC39) AG26(NC40) AG27(PEX_REFCLK_SSCP16) AH26(NC41) AH27(PEX_REFCLK_SSCN16) AJ14(NC42) AL32(NC43) AM32(NC44) G26(PEX_REFCLK_SSCN23) G27(PEX_REFCLK_SSCP22) G28(PEX_REFCLK_SSCN22) H26(PEX_REFCLK_SSCP23) L27(PEX_REFCLK_SSCP21) L28(PEX_REFCLK_SSCN21) R27(PEX_REFCLK_SSCP20) R28(PEX_REFCLK_SSCN20) W27(PEX_REFCLK_SSCP19) W28(PEX_REFCLK_SSCN19)

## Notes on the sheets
sheet 21
- PEX8796
